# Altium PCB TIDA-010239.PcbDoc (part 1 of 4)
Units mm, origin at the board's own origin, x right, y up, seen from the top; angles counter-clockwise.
Board outline 160 x 175 mm, 4 copper layers (Top Layer, Inside 1, Inside 2, Bottom Layer), stack 1.787 mm thick; 299 components, 146 nets, 710 pads, 164 vias.
Unrouted connection lines stored in the file: 9.
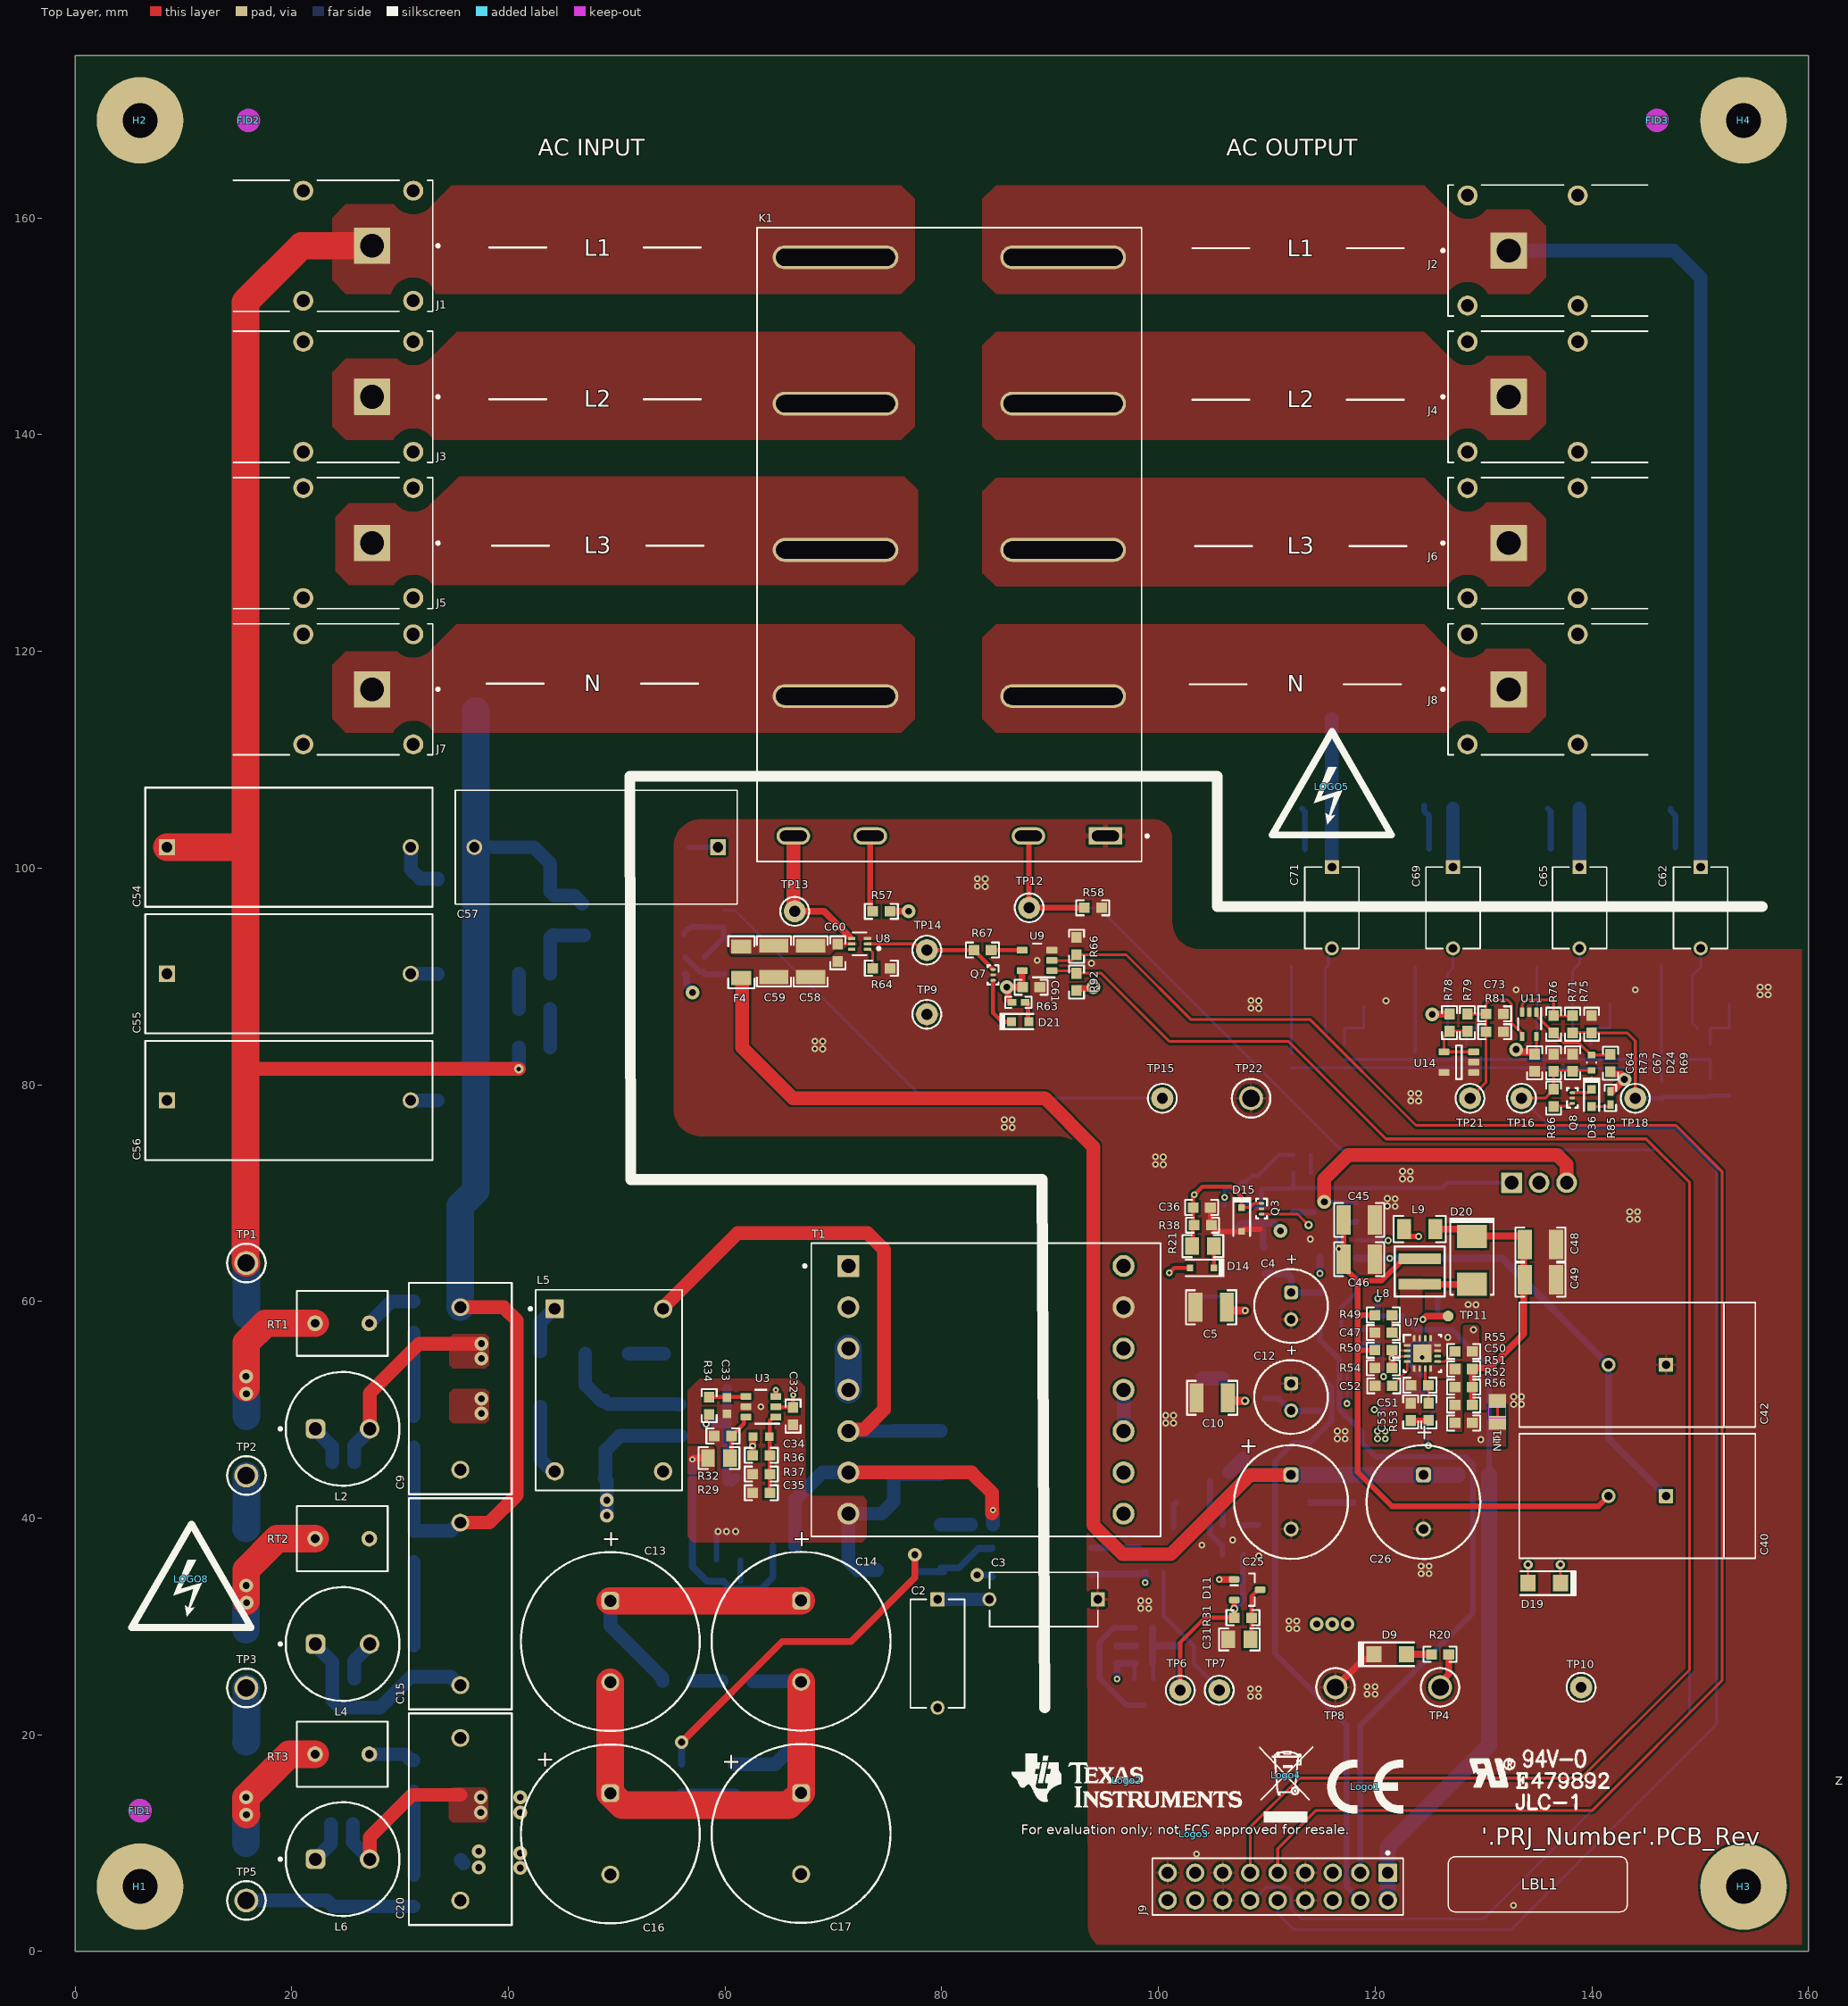
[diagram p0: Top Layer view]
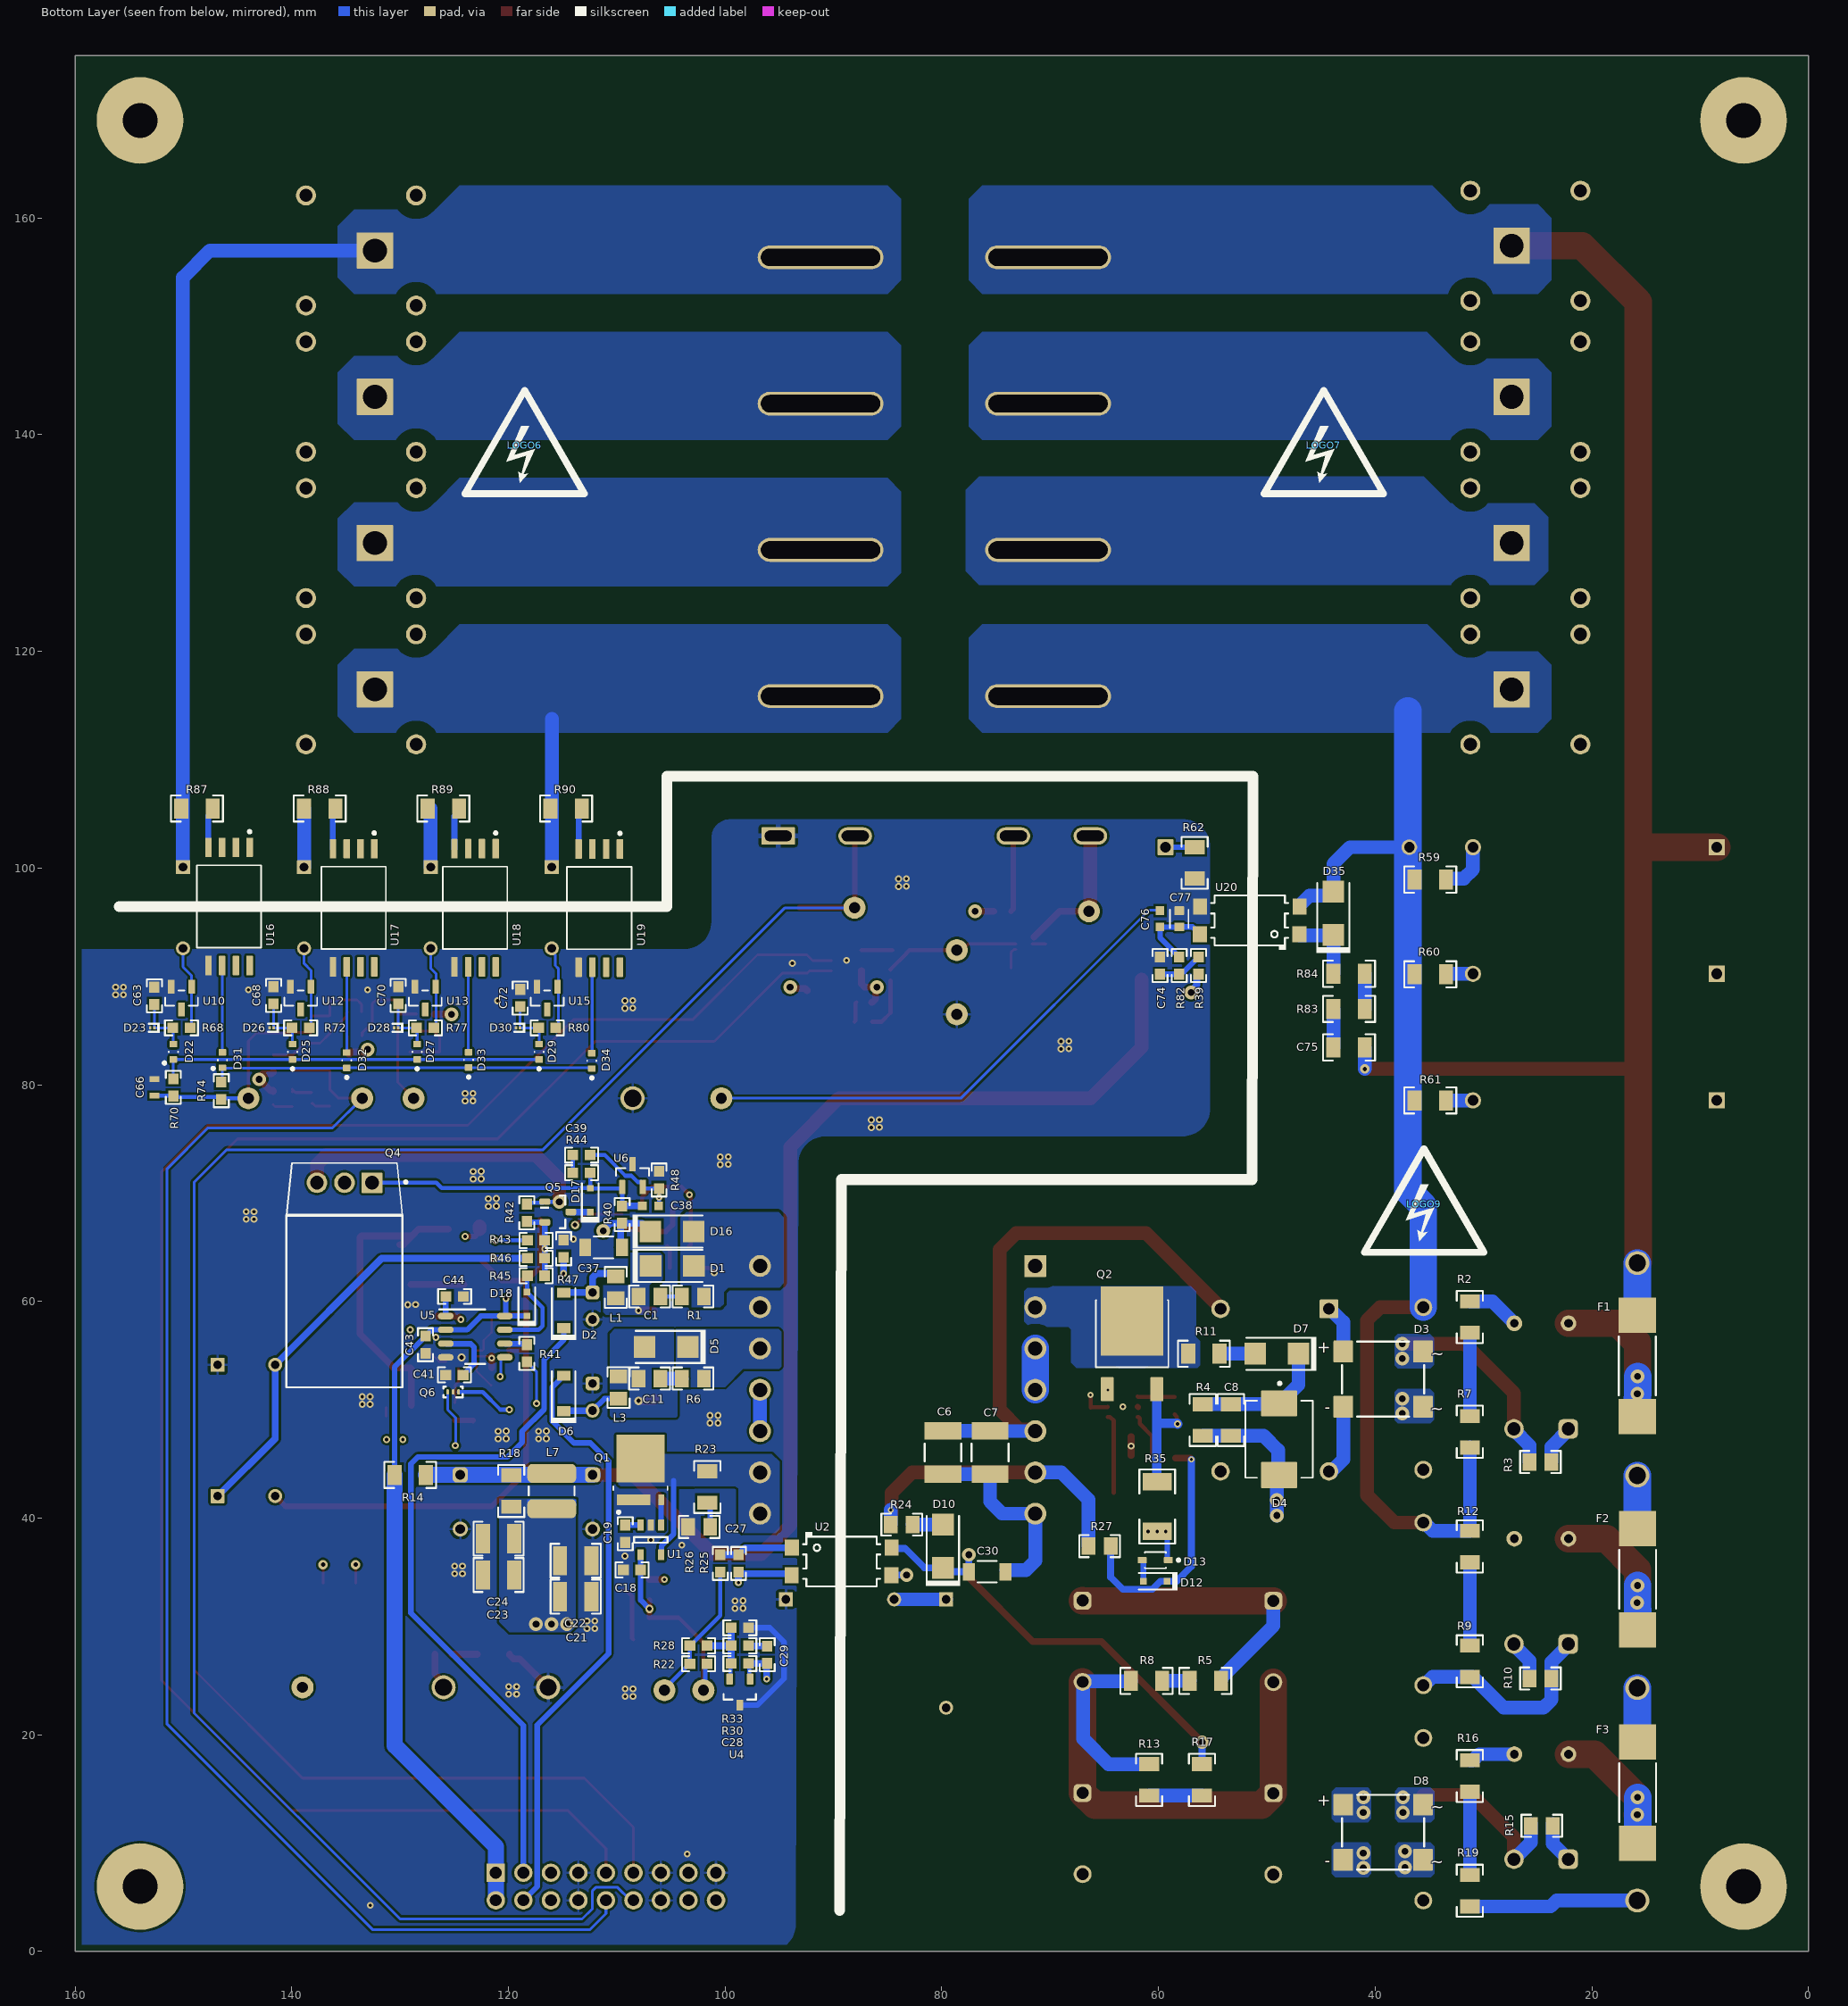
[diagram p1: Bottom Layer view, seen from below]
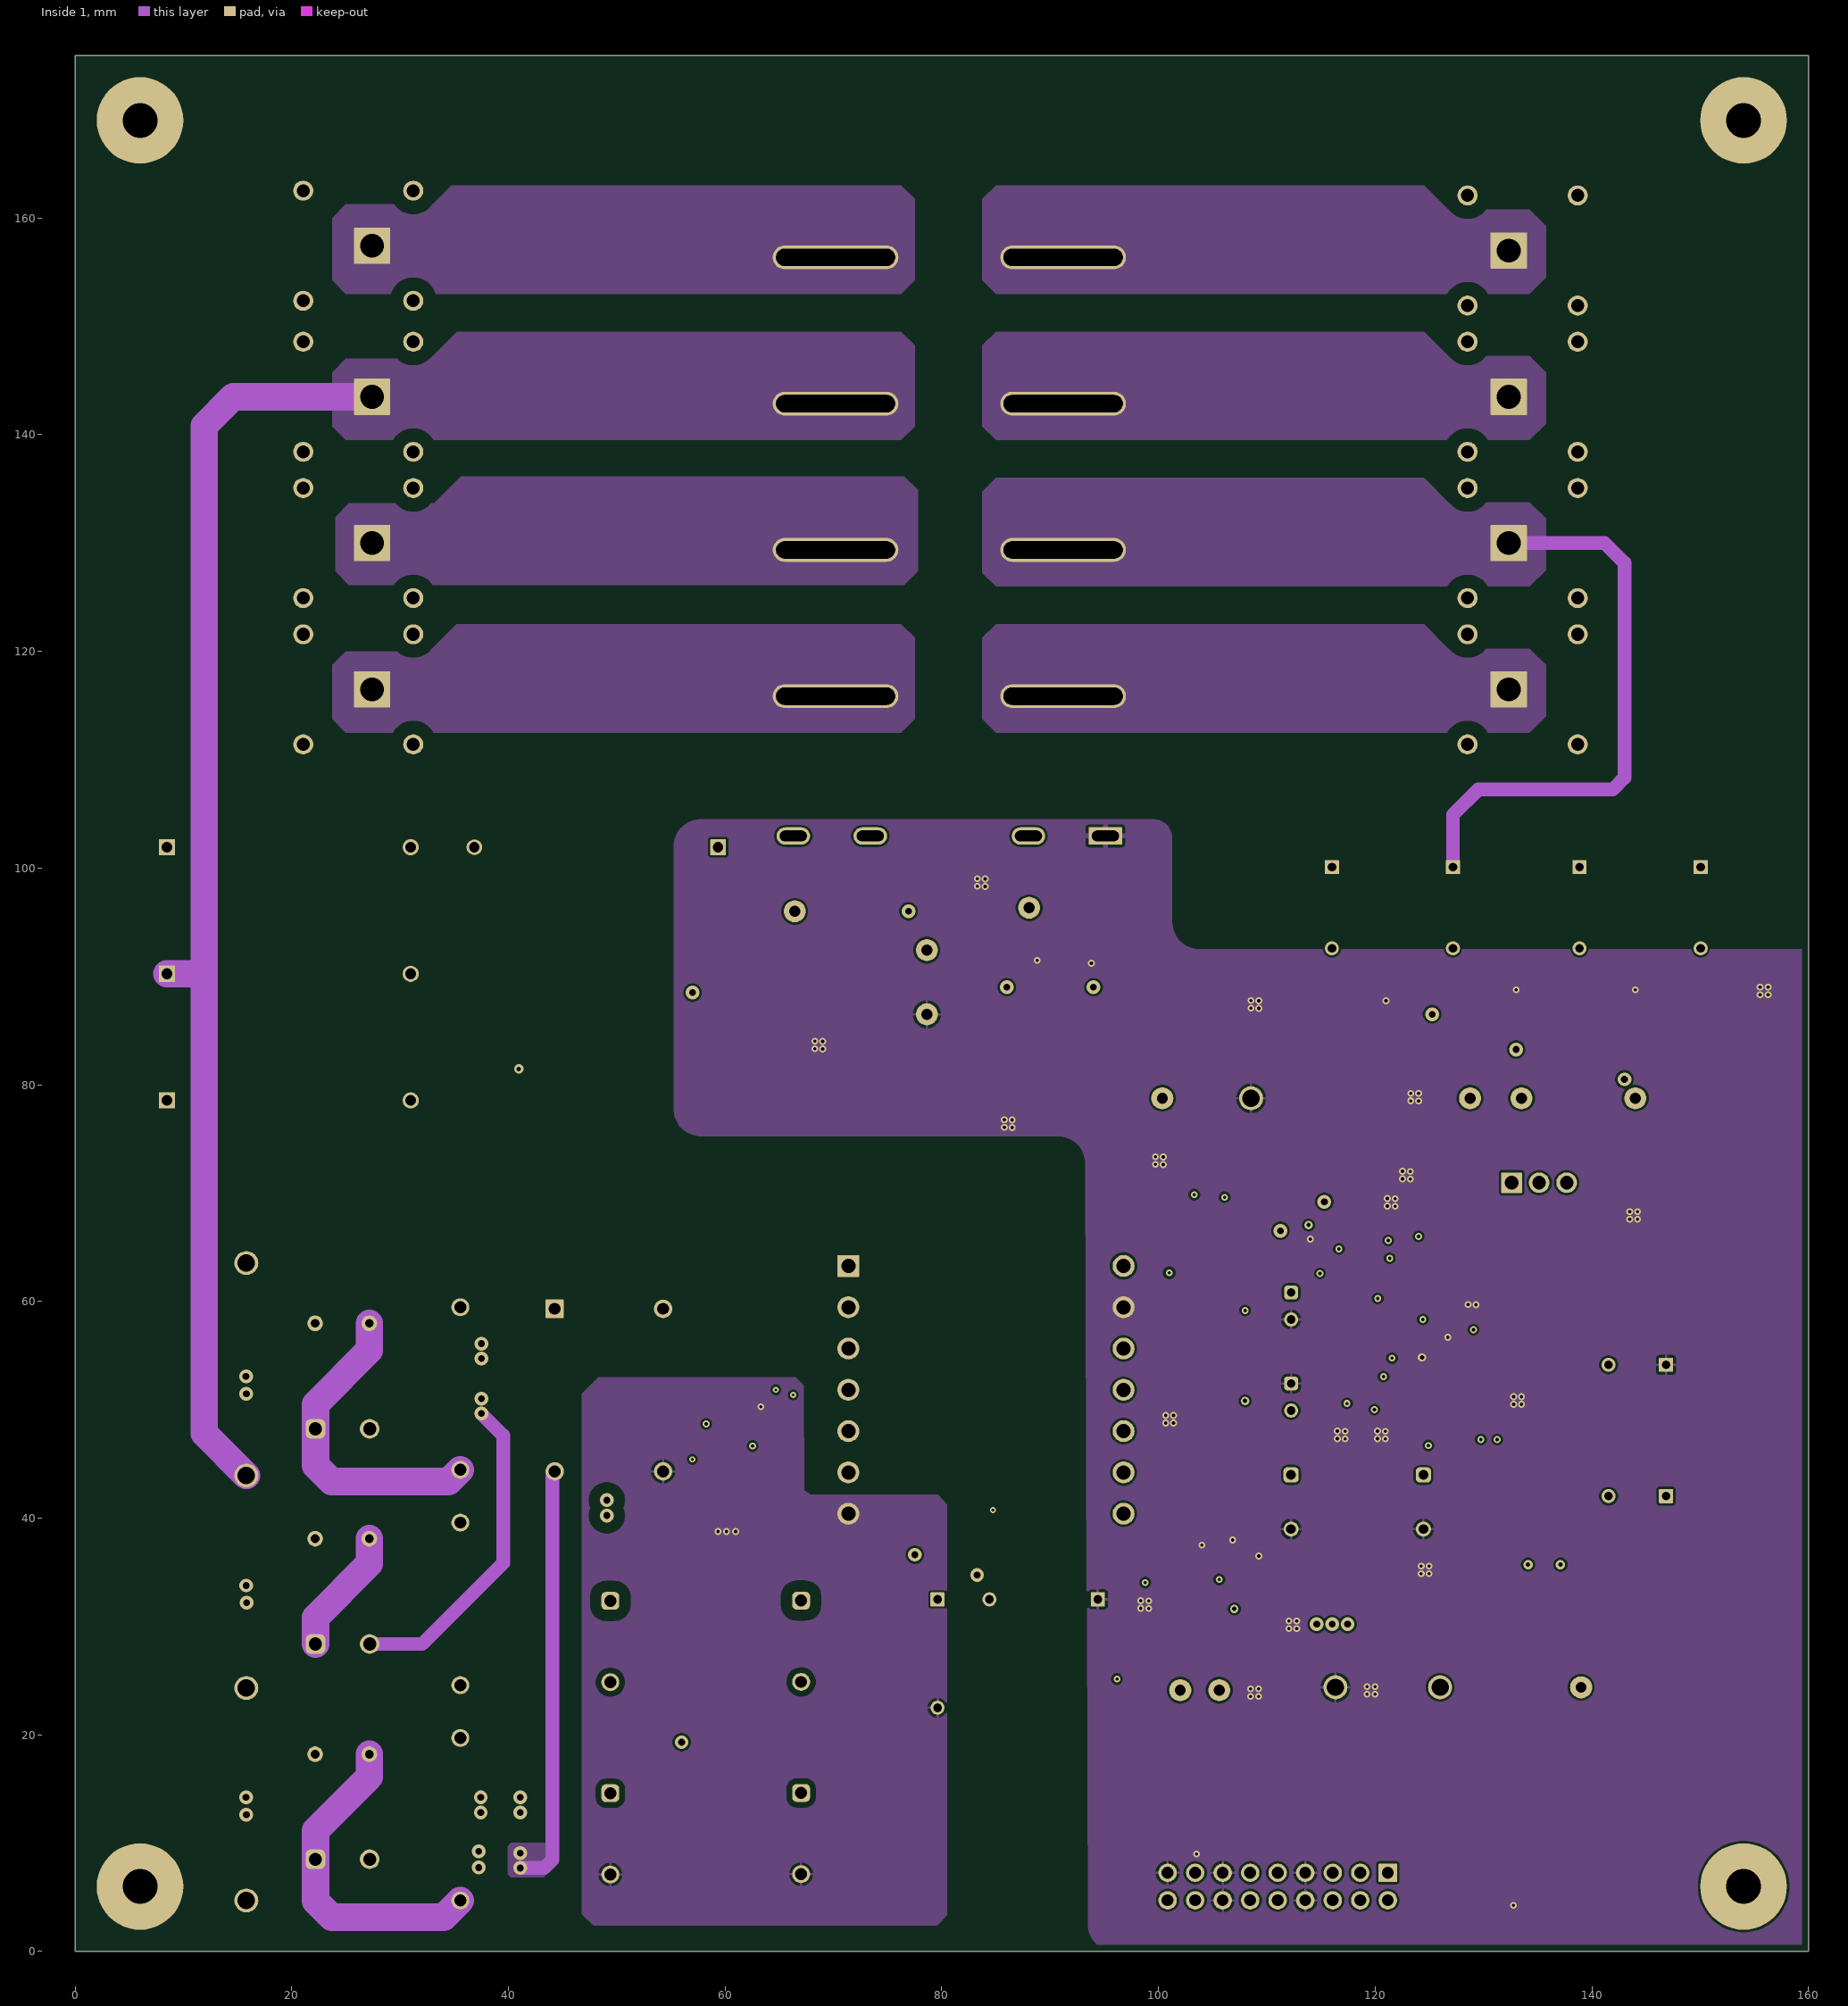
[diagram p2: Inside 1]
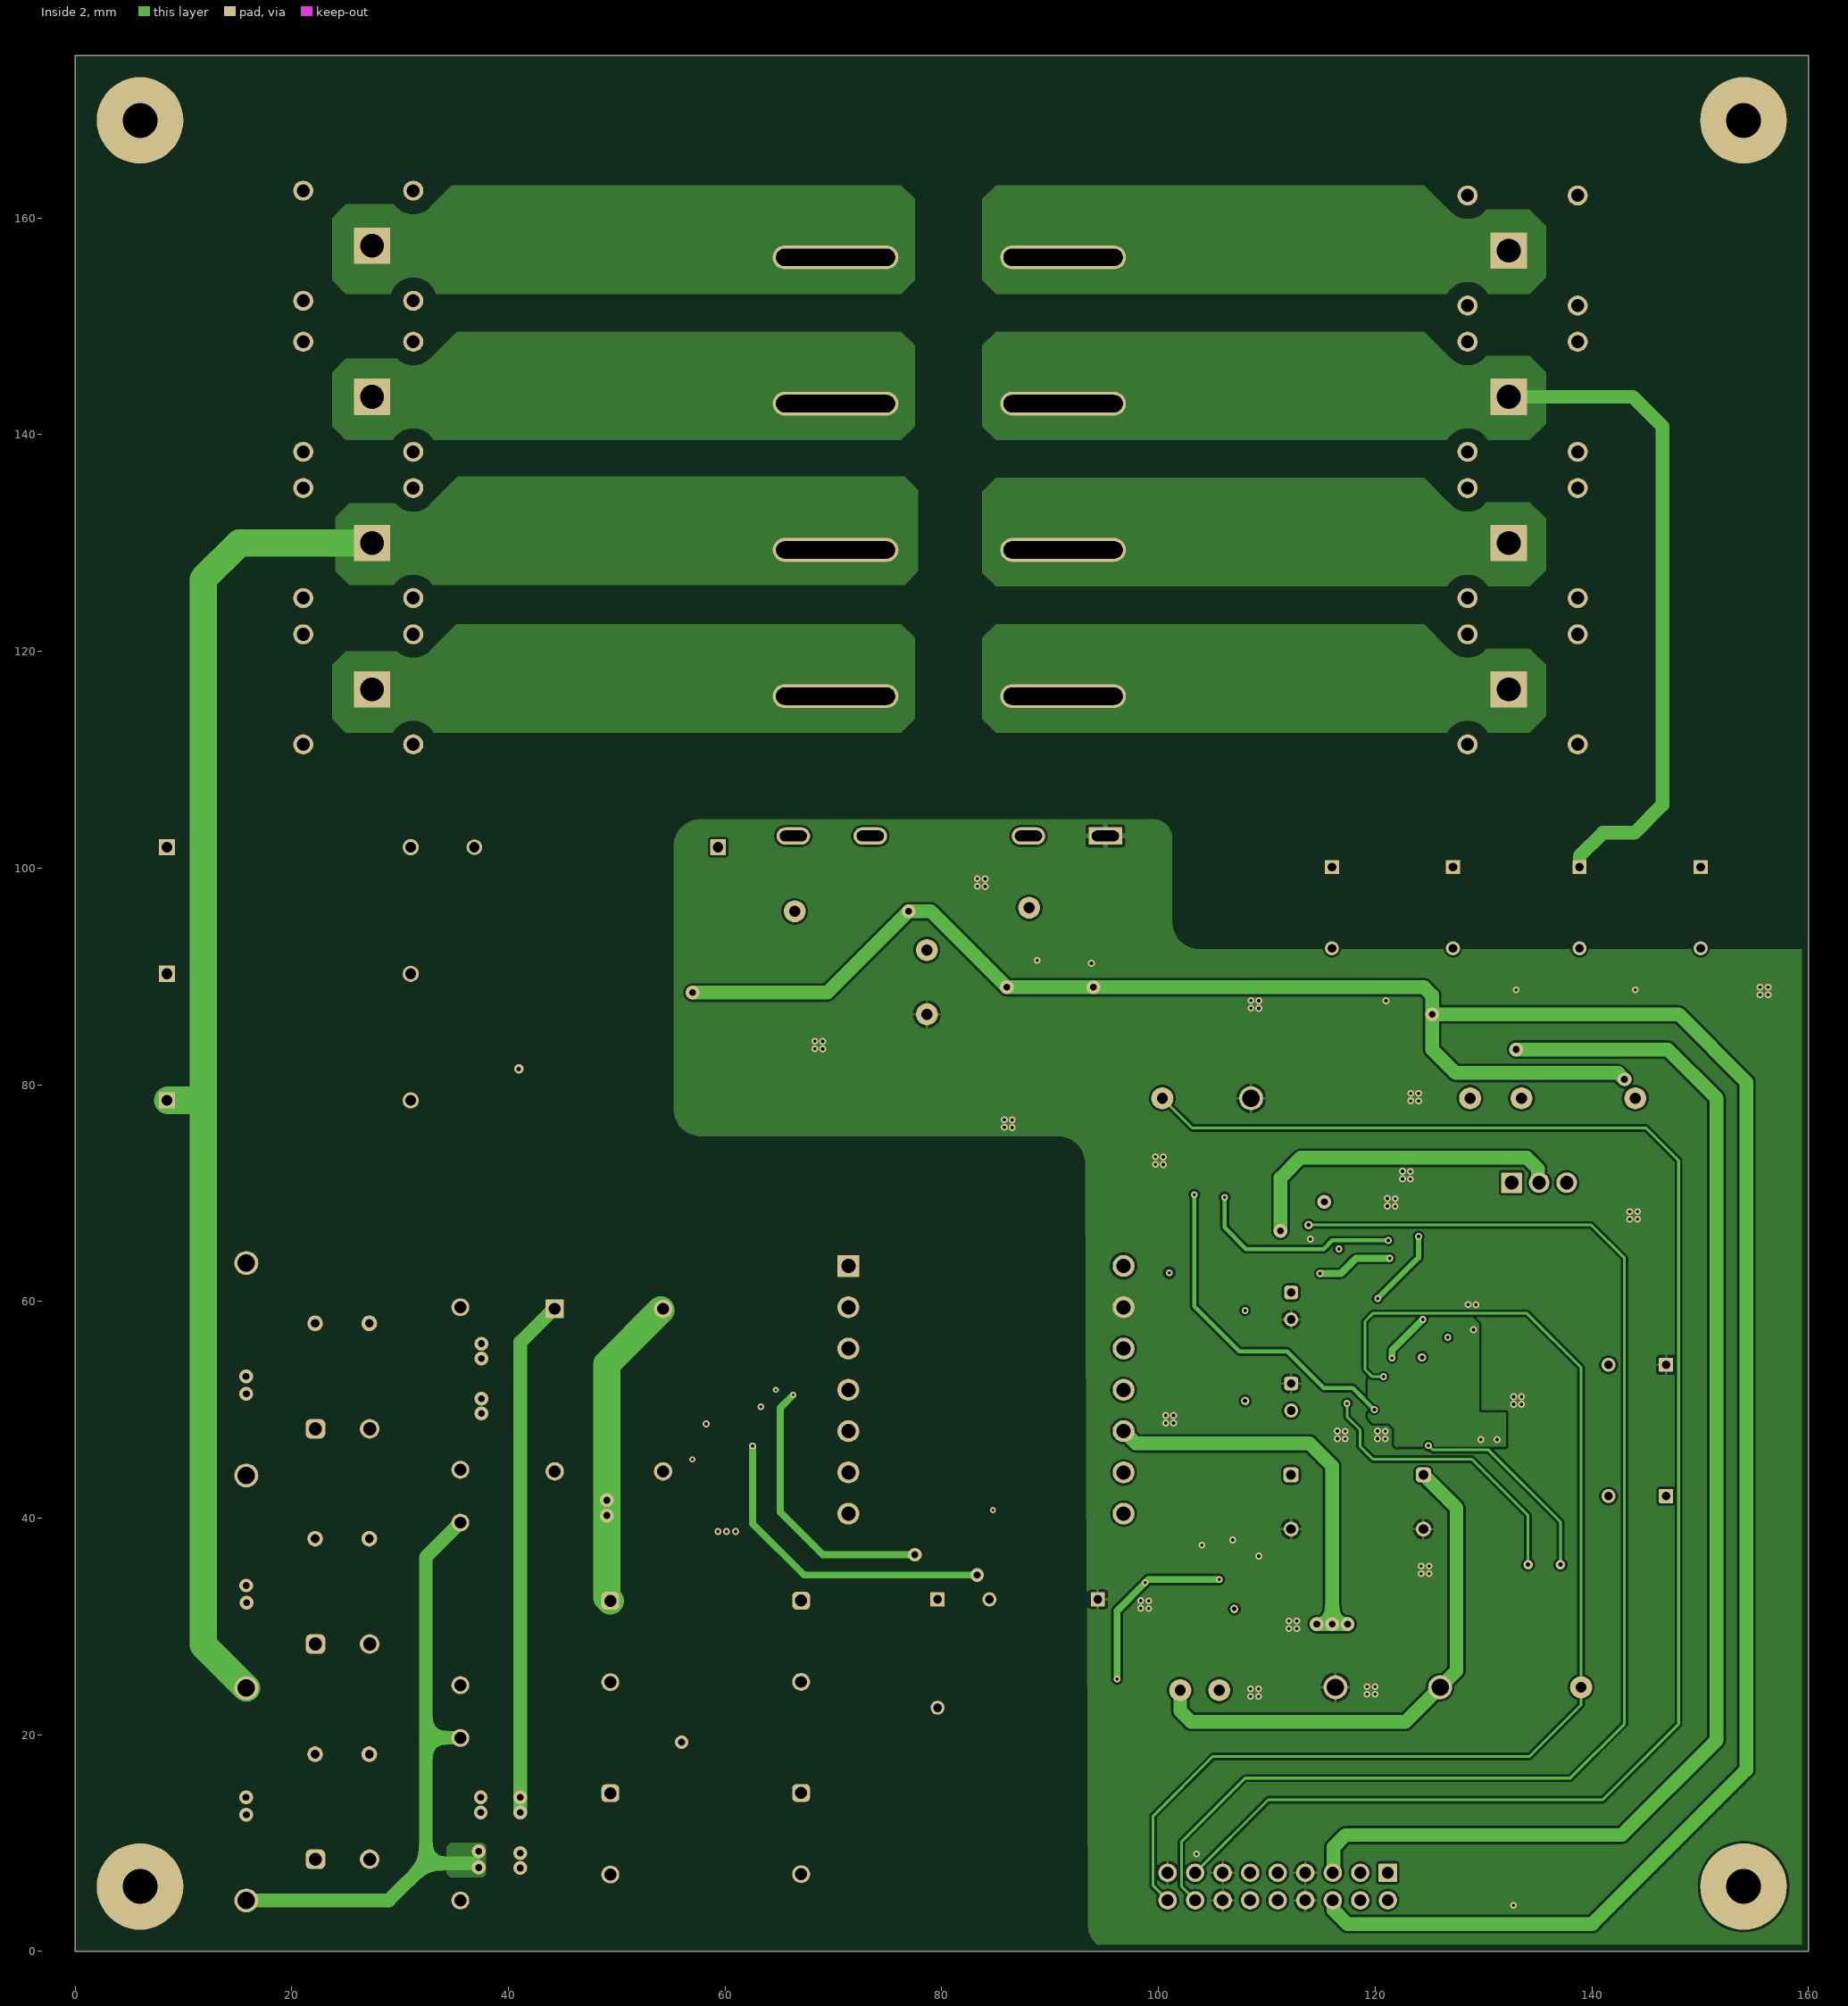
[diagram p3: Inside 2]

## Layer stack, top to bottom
Top Solder: solder mask 0.0102, Solder Resist, Dk 3.5
Top Layer: signal copper 0.0356
Dielectric 1: prepreg 0.0711, PP-006, Dk 4.1
Inside 1: signal copper 0.035
Dielectric1: core 1.5037, FR-4 High Tg, Dk 4.8
Inside 2: signal copper 0.035
Dielectric 2: prepreg 0.0711, PP-006, Dk 4.1
Bottom Layer: signal copper 0.0356
Bottom Solder: solder mask 0.0102, Solder Resist, Dk 3.5

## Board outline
0,0 0,175 160,175 160,0

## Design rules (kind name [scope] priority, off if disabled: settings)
AcuteAngle [All] p1: minimum=4.50000000000000E+0001 checktracksonly=FALSE
AssemblyTestPointUsage [All] p1: valid=2
BoardOutlineClearance BoardOutlineClearance_MountingHoles [OnCopper and InComponentClass('Mounting Holes')] p1: gap=1.016 ignorepadtopadclearanceinfootprint=FALSE
BoardOutlineClearance BoardOutlineClearance_Poly [OnCopper and IsPoly] p2: gap=0.635 ignorepadtopadclearanceinfootprint=FALSE
BoardOutlineClearance [OnCopper and Not InComponentClass('Logo') and not InComponentClass('FiducialMark') and not InRegion(1000,500,4000,800) and not InPoly] p3: gap=1.905 ignorepadtopadclearanceinfootprint=FALSE
Clearance "Schematic Clearance Constraint_9" [InNet('NetC8_2')] p1: gap=1.016 ignorepadtopadclearanceinfootprint=FALSE
Clearance "Schematic Clearance Constraint_8" [InNet('NetT1_3')] p2: gap=1.016 ignorepadtopadclearanceinfootprint=FALSE
Clearance "Schematic Clearance Constraint_7" [InNet('NetC6_1')] p3: gap=1.016 ignorepadtopadclearanceinfootprint=FALSE
Clearance "Schematic Clearance Constraint_6" [InNet('NetD7_2')] p4: gap=1.016 ignorepadtopadclearanceinfootprint=FALSE
Clearance "Schematic Clearance Constraint_5" [InNet('NetQ2_4')] p5: gap=1.016 ignorepadtopadclearanceinfootprint=FALSE
Clearance "Schematic Clearance Constraint_4" [InNet('NetR5_1')] p6: gap=1.016 ignorepadtopadclearanceinfootprint=FALSE
Clearance "Schematic Clearance Constraint_3" [InNet('NetR13_1')] p7: gap=0.508 ignorepadtopadclearanceinfootprint=FALSE
Clearance "Schematic Clearance Constraint_2" [InNet('NetC13_2')] p8: gap=0.508 ignorepadtopadclearanceinfootprint=FALSE
Clearance "Schematic Clearance Constraint" [InNet('+14V_SW')] p9: gap=0.254 ignorepadtopadclearanceinfootprint=FALSE
Clearance Clearance_HV_AC [InNetClass('HV')] p10: gap=1.25 ignorepadtopadclearanceinfootprint=FALSE
Clearance Clearance_Keepouts [((IsTrack Or IsArc) And Not InPoly) And IsFree and IsKeepOut vs ((IsTrack Or IsArc) And Not InPoly) And IsFree and IsKeepOut] p11: gap=0 ignorepadtopadclearanceinfootprint=FALSE
Clearance Clearance_Poly [InPolygon] p12: gap=0.203 ignorepadtopadclearanceinfootprint=FALSE
Clearance Clearance_FiducialMark [IsKeepOut and InComponentClass('FiducialMark') vs IsPad and InComponentClass('FiducialMark')] p13: gap=0 ignorepadtopadclearanceinfootprint=FALSE
Clearance [All] p14: gap=0.127 ignorepadtopadclearanceinfootprint=FALSE
ComponentClearance ComponentClearance_MountingHoles_FiducialMarks [InComponentClass('Mounting Holes') vs InComponentClass('FiducialMark')] p1: gap=1.27 collisioncheckmode=3 verticalgap=0.254 showdistances=FALSE
ComponentClearance ComponentClearance_Shunt [InComponentClass('Header') vs InComponentClass('Shunt')] p2: gap=0 collisioncheckmode=3 verticalgap=0 showdistances=FALSE
ComponentClearance ComponentClearance_Logo [InComponentClass('Logo')] p3: gap=1.27 collisioncheckmode=3 verticalgap=0.254 showdistances=FALSE
ComponentClearance ComponentClearance_ScrewToNut [(HasFootprint('NY PMS 440 0025 PH')) vs (HasFootprint('Keystone_1902C'))] p4: gap=0.127 collisioncheckmode=3 verticalgap=0.254 showdistances=FALSE
ComponentClearance ComponentClearance_MountingHoles [InComponentClass('Mounting Holes')] p5: gap=4 collisioncheckmode=3 verticalgap=2540 showdistances=FALSE
ComponentClearance ComponentClearance_SmallPassives [HasFootprint('0201*') or HasFootprint('0402*') or HasFootprint('0508') or HasFootprint('0603*') or HasFootprint('0612') or HasFootprint('0805*') or HasFootprint('0815*') or HasFootprint('0830*') or HasFootprint('1206*') or HasFootprint('1210*') or HasFootprint('1808*') or HasFootprint('1812*') or HasFootprint('1825*') or HasFootprint('2010*') or HasFootprint('2220*') or HasFootprint('2225*') or HasFootprint('2512*') or HasFootprint('2728*') or HasFootprint('3518*') vs HasFootprint('0201*') or HasFootprint('0402*') or HasFootprint('0508') or HasFootprint('0603*') or HasFootprint('0612') or HasFootprint('0805*') or HasFootprint('0815*') or HasFootprint('0830*') or HasFootprint('1206*') or HasFootprint('1210*') or HasFootprint('1808*') or HasFootprint('1812*') or HasFootprint('1825*') or HasFootprint('2010*') or HasFootprint('2220*') or HasFootprint('2225*') or HasFootprint('2512*') or HasFootprint('2728*') or HasFootprint('3518*')] p6: gap=0.38 collisioncheckmode=3 verticalgap=0.254 showdistances=FALSE
ComponentClearance ComponentClearance_THtoSMT [IsThruComponent vs IsSMTComponent] p7: gap=0.635 collisioncheckmode=3 verticalgap=0.762 showdistances=FALSE
ComponentClearance ComponentClearance_THtoTH [IsThruComponent vs IsThruComponent] p8 off: gap=0.762 collisioncheckmode=3 verticalgap=0.762 showdistances=FALSE
ComponentClearance [All] p9 off: gap=0.762 collisioncheckmode=3 verticalgap=0.254 showdistances=FALSE
DiffPairsRouting [All] p1: maxlimit=2.54 minlimit=0.254 mostfreqgap=0.254 toplayer_minwidth=0.381 toplayer_maxwidth=0.381 toplayer_prefwidth=0.381 midlayer1_minwidth=0.381 midlayer1_maxwidth=0.381 midlayer1_prefwidth=0.381 midlayer2_minwidth=0.381 midlayer2_maxwidth=0.381 midlayer2_prefwidth=0.381 bottomlayer_minwidth=0.381 bottomlayer_maxwidth=0.381 bottomlayer_prefwidth=0.381 maxuncoupledlength=25.4
FabricationTestPointUsage TestPointUsage [All] p1: valid=2 allowmultiple=FALSE
FabricationTestpoint Testpoint [All] p1: side=3 testpointundercomponent=TRUE minsize=1.016 maxsize=2.54 preferedsize=1.524 minholesize=0 maxholesize=1.016 preferedholesize=0.813 testpointgrid=0.025 allowsidetop=TRUE allowsidebottom=TRUE usegrid=TRUE gridtolerance=0
FanoutControl Fanout_LCC [IsLCC] p1: bgadir=Out bgaviamode=Centered fanoutstyle=Auto fanoutdirection=Alternating viagrid=0.025 // Fanout_LCC (Default Rule)
FanoutControl Fanout_BGA [IsBGA] p2: bgadir=Out bgaviamode=Centered fanoutstyle=Auto fanoutdirection=Alternating viagrid=0.025 // Fanout_BGA (Default Rule)
FanoutControl Fanout_Default [All] p4: bgadir=Out bgaviamode=Centered fanoutstyle=Auto fanoutdirection=Alternating viagrid=0.025 // Fanout_Default (Default Rule)
FanoutControl Fanout_Small [(CompPinCount < 5)] p5: bgadir=Out bgaviamode=Centered fanoutstyle=Auto fanoutdirection=OutThenIn viagrid=0.025 // Fanout_Small (Default Rule)
Height [All] p1: minheight=0 maxheight=27.94 prefheight=12.7
HoleSize HoleSize_Relay [(InNetClass('HV') AND InPadClass('All Pads'))] p1: absolutevalues=TRUE maxlimit=11.049 minlimit=0.025 maxpercent=80.000 minpercent=20.000
HoleSize [All] p2: absolutevalues=TRUE maxlimit=6.375 minlimit=0.2 maxpercent=80.000 minpercent=20.000
MinimumAnnularRing MinimumAnnularRing_ThermalPadVias [IsVia and InAnyComponent] p1: minimumring=0.1
MinimumAnnularRing [All] p2: minimumring=0.1
MinimumSolderMaskSliver MinimumSolderMaskSliver_ISO1212 [HasFootprint('DBQ0016A_N')] p1: minsoldermaskwidth=0.032
MinimumSolderMaskSliver MinimumSolderMaskSliver_TPS6513 [HasFootprint('RGE0024B')] p2: minsoldermaskwidth=0.046
MinimumSolderMaskSliver MinimumSolderMaskSliver_TLV7011 [HasFootprint('DCK0005A_N')] p3: minsoldermaskwidth=0.046
MinimumSolderMaskSliver MinimumSolderMaskSliver_TPS55330 [HasFootprint('RTE0016C_NV')] p4: minsoldermaskwidth=0.056
MinimumSolderMaskSliver MinimumSolderMaskSliver_INA293 [HasFootprint('DBV0005A_M')] p5: minsoldermaskwidth=0.097
MinimumSolderMaskSliver MinimumSolderMaskSliver_TPS7A3901_1 [HasFootprint('DSC0010J')] p6: minsoldermaskwidth=0.056
MinimumSolderMaskSliver MinimumSolderMaskSliver_Res [HasFootprint('RESC1005X40X25NL05T10')] p7: minsoldermaskwidth=0.046
MinimumSolderMaskSliver MinimumSolderMaskSliver_Logo [InComponentClass('Logo') vs InComponentClass('Logo')] p8: minsoldermaskwidth=0.018
MinimumSolderMaskSliver [All] p9: minsoldermaskwidth=0.1
PlaneConnect [All] p1: planeconnectstyle=Direct reliefexpansion=0.254 reliefentries=4 reliefconductorwidth=0.254 reliefairgap=0.254
PolygonConnect PolygonConnect_4 [All vs IsNamedPolygon('LAYER_2_LINE1_IN_P1412') Or IsNamedPolygon('LAYER_2_LINE1_OUT_P1420') Or IsNamedPolygon('LAYER_2_LINE2_IN_P1414') Or IsNamedPolygon('LAYER_2_LINE2_OUT_P1422') Or IsNamedPolygon('LAYER_2_LINE3_IN_P1416') Or IsNamedPolygon('LAYER_2_LINE3_OUT_P1424') Or IsNamedPolygon('LAYER_2_N_IN_P1418') Or IsNamedPolygon('LAYER_2_N_OUT_P1426')] p1: connectstyle=Direct reliefconductorwidth=0.254 reliefentries=4 polygonreliefangle="90 Angle" airgapwidth=0.254
PolygonConnect PolygonConnect_3 [All vs IsNamedPolygon('LAYER_1_LINE1_IN_P1411') Or IsNamedPolygon('LAYER_1_LINE1_OUT_P1419') Or IsNamedPolygon('LAYER_1_LINE2_IN_P1413') Or IsNamedPolygon('LAYER_1_LINE2_OUT_P1421') Or IsNamedPolygon('LAYER_1_LINE3_IN_P1415') Or IsNamedPolygon('LAYER_1_LINE3_OUT_P1423') Or IsNamedPolygon('LAYER_1_N_IN_P1417') Or IsNamedPolygon('LAYER_1_N_OUT_P1425')] p2: connectstyle=Direct reliefconductorwidth=0.254 reliefentries=4 polygonreliefangle="90 Angle" airgapwidth=0.254
PolygonConnect PolygonConnect_2 [All vs IsNamedPolygon('TOP_LAYER_N_IN_P1382') Or IsNamedPolygon('TOP_LAYER_N_OUT_P1366') Or IsNamedPolygon('BOTTOM_LAYER_N_IN_P1390') Or IsNamedPolygon('BOTTOM_LAYER_N_OUT_P1392')] p3: connectstyle=Direct reliefconductorwidth=0.254 reliefentries=4 polygonreliefangle="90 Angle" airgapwidth=0.254
PolygonConnect PolygonConnect_1 [All vs IsNamedPolygon('TOP_LAYER_LINE1_IN_P1378') Or IsNamedPolygon('TOP_LAYER_LINE1_OUT_P1370') Or IsNamedPolygon('TOP_LAYER_LINE2_IN_P1374') Or IsNamedPolygon('TOP_LAYER_LINE2_OUT_P1330') Or IsNamedPolygon('TOP_LAYER_LINE3_IN_P1380') Or IsNamedPolygon('TOP_LAYER_LINE3_OUT_P1372') Or IsNamedPolygon('BOTTOM_LAYER_LINE1_IN_P1256') Or IsNamedPolygon('BOTTOM_LAYER_LINE1_OUT_P1398') Or IsNamedPolygon('BOTTOM_LAYER_LINE2_IN_P1386') Or IsNamedPolygon('BOTTOM_LAYER_LINE2_OUT_P1396') Or IsNamedPolygon('BOTTOM_LAYER_LINE3_IN_P1388') Or IsNamedPolygon('BOTTOM_LAYER_LINE3_OUT_P1394')] p4: connectstyle=Direct reliefconductorwidth=0.254 reliefentries=4 polygonreliefangle="90 Angle" airgapwidth=0.254
PolygonConnect [InNetClass('All Nets')] p5: thpad.connectstyle=Relief thpad.reliefconductorwidth=0.254 thpad.reliefentries=4 thpad.polygonreliefangle="90 Angle" thpad.airgapwidth=0.254 smdpad.connectstyle=Direct smdpad.reliefconductorwidth=0.254 smdpad.reliefentries=4 smdpad.polygonreliefangle="90 Angle" smdpad.airgapwidth=0.254 via.connectstyle=Direct via.reliefconductorwidth=0.254 via.reliefentries=4 via.polygonreliefangle="90 Angle" via.airgapwidth=0.254
RoutingVias ThermalPadVias [IsVia and InAnyComponent] p1: holewidth=0.2 width=0.5 viastyle="Through Hole" minholewidth=0.2 minwidth=0.5 maxholewidth=0.33 maxwidth=0.6
RoutingVias [All] p2: holewidth=0.406 width=0.864 viastyle="Through Hole" minholewidth=0.152 minwidth=0.381 maxholewidth=1.016 maxwidth=1.651
SilkToBoardRegionClearance [Not ((IsComment or IsDesignator) And (Hide <> 'False')) and not InRegion(1000,500,4000,800)] p1:
SilkToSilkClearance SilkToSilkClearance_Pb-FreeLogo [(HasFootprint('Pb-Free_Overlay_Medium') OR HasFootprint('Pb-Free_Overlay_Small')) vs (HasFootprint('Pb-Free_Overlay_Medium') OR HasFootprint('Pb-Free_Overlay_Small'))] p1: silktosilkclearance=0
SilkToSilkClearance [All] p2: silktosilkclearance=0.051
SilkToSolderMaskClearance SilkToComponentPadClearance_FillArea [IsFill and InAnycomponent] p1: minsilkscreentomaskgap=0.038 clearancetoexposedcopper=TRUE
SilkToSolderMaskClearance SilkToComponentPadClearance_Pad [IsPad and InAnycomponent] p2: minsilkscreentomaskgap=0.076 clearancetoexposedcopper=TRUE
SilkToSolderMaskClearance SilkToComponentPadClearance_1 [(IsPad or IsFill or IsRegion) and InAnycomponent] p3: minsilkscreentomaskgap=0.127 clearancetoexposedcopper=TRUE
SilkToSolderMaskClearance "Silk to Solder Mask Opening" [All] p4: minsilkscreentomaskgap=0.076 clearancetoexposedcopper=FALSE
SolderMaskExpansion [All] p1 off: expansion=0.05 istentingtop=FALSE
SupplyNets "Schematic Supply Nets_7" [InNet('5V')] p1: voltage=0.000
SupplyNets "Schematic Supply Nets_5" [InNet('PGND')] p2: voltage=0.000
SupplyNets "Schematic Supply Nets_3" [InNet('AGND2')] p3: voltage=0.000
SupplyNets "Schematic Supply Nets_2" [InNet('12V')] p4: voltage=0.000
SupplyNets "Schematic Supply Nets_1" [InNet('3V3')] p5: voltage=0.000
SupplyNets "Schematic Supply Nets" [InNet('GND')] p6: voltage=0.000
Width Width_5V [All] p1 off: maxlimit=2.54 minlimit=0.254 preferedwidth=0.762
Width Width_-12a [InNet('-12Va')] p2 off: maxlimit=1.27 minlimit=0.254 preferedwidth=0.508
Width Width_12a [InNet('+12Va')] p3 off: maxlimit=1.27 minlimit=0.254 preferedwidth=0.508
Width Width_12VP [InNet('12V_In')] p4 off: maxlimit=1.27 minlimit=0.254 preferedwidth=0.762
Width Width_3_3 [InNet('3V3')] p5 off: maxlimit=2.54 minlimit=0.254 preferedwidth=0.762
Width Width_GND [InNet('PGND')] p6 off: maxlimit=0.762 minlimit=0.254 preferedwidth=0.508
Width Width_AC [InNetClass('HV')] p7 off: maxlimit=5.08 minlimit=0.508 preferedwidth=2.54
Width [All] p8 off: maxlimit=0.508 minlimit=0.203 preferedwidth=0.254 checkconnectedcopper=TRUE
14 further rules are at their usual default settings.

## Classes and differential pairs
component class TIDA-010239_HPGP_ZC: C74 C75 C76 C77 D35 R39 R82 R83 R84 TP15 U20
net class HV: LINE1_IN LINE1_OUT LINE2_IN LINE2_OUT LINE3_IN LINE3_OUT N_IN N_OUT NetR87_1 NetR88_1 NetR89_1 NetR90_1
component class TIDA-010239_Weld_Detection: C62 C63 C64 C65 C66 C67 C68 C69 C70 C71 C72 C73 D22 D23 D24 D25 D26 D27 D28 D29 D30 D36 Q8 R68 R69 R70 R71 R72 R73 R74 R75 R76 R77 R78 R79 R80 R81 R85 R86 TP16 TP18 TP21 TP22 U10 U11 U12 U13 U14 U15
component class TIDA-010239_Weld_Detection_B: D31 D32 D33 D34 R87 R88 R89 R90 U16 U17 U18 U19
component class TIDA-010239_Relay_DRV: C54 C55 C56 C57 C58 C59 C60 C61 D21 F4 J1 J2 J3 J4 J5 J6 J7 J8 K1 Q7 R57 R58 R59 R60 R61 R62 R63 R64 R66 R67 R92 TP12 TP13 TP14 U8 U9
component class TIDA-010239_PWR_Flyback: C1 C2 C3 C4 C5 C6 C7 C8 C9 C10 C11 C12 C13 C14 C15 C16 C17 C18 C19 C20 C21 C22 C23 C24 C25 C26 C27 C28 C29 C30 C31 C32 C33 C34 C35 D1 D2 D3 D4 D5 D6 D7 D8 D9 D10 D11 D12 D13 F1 F2 F3 L1 L2 L3 L4 L5 L6 L7 Q1 Q2 R1 R2 R3 R4 R5 R6 R7 R8 R9 R10 R11 R12 R13 R14 R15 R16 R17 R18 R19 R20 R22 R23 R24 R25 R26 R27 R28 R29 R30 R31 R32 R33 R34 R35 R36 R37 RT1 RT2 RT3 T1 TP1 TP2 TP3 TP4 TP5 TP6 TP7 TP8 TP9 U1 U2 U3 U4
component class TIDA-010239_PWR_Backup: C36 C37 C38 C39 C40 C41 C42 C43 C44 C45 C46 C47 C48 C49 C50 C51 C52 C53 D14 D15 D16 D17 D18 D19 D20 L8 L9 NT1 Q3 Q4 Q5 Q6 R21 R38 R40 R41 R42 R43 R44 R45 R46 R47 R48 R49 R50 R51 R52 R53 R54 R55 R56 TP10 TP11 U5 U6 U7
component class TIDA-010239_Connector: J9
component class "Mounting Holes": H1 H2 H3 H4
component class Logo: Logo2
component class TIDA-010239_Hardware: FID1 FID2 FID3 H1 H2 H3 H4 LBL1 Logo1 Logo2 Logo3 Logo4 LOGO5 LOGO6 LOGO7 LOGO8 LOGO9 ZZ1 ZZ2 ZZ3 ZZ4
component class FiducialMark: FID1 FID2 FID3
component class AssemblyNote: ZZ1 ZZ2 ZZ3 ZZ4
component class Label: LBL1

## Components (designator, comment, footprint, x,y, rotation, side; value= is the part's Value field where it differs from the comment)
C1 "GRM21A5C2E680JW01D" 0805_HV 106.973,60.45 r180 bottom value=68pF
C2 "DE1E3RA332MN4AP01F" FP-DE1E3RA332MN4AP01F_RADIAL_CAP_10MM0_5MM0_10MM0-MFG 79.6,27.5 r270 top value=3.3nF
C3 "DE1E3RA332MN4AP01F" FP-DE1E3RA332MN4AP01F_RADIAL_CAP_10MM0_5MM0_10MM0-MFG 89.4,32.5 r180 top value=3.3nF
C4 "860010473007" WCAP-ATG8_D6.3H11 112.233,59.58 r90 top locked value=100µF
C5 "CC1210KKX7R8BB226" 1210_270 104.853,59.46 r180 top value=22uF
C6 "C1812W104KDRACTU" 1812_254 79.891,46.044 r270 bottom value=0.1uF
C7 "C1812W104KDRACTU" 1812_254 75.551,46.044 r270 bottom value=0.1uF
C8 "VJ1206Y102KXEAT5Z" 1206 53.318,49.05 r90 bottom value=1000pF
C9 "890493425009CS" WCAP-FTBE_L18W8.5H15 35.563,51.96 r90 top value=100nF
C10 "CC1210KKX7R8BB226" 1210_270 104.95,51.1 r0 top value=22uF
C11 "GRM21A5C2E680JW01D" 0805_HV 106.973,52.89 r180 bottom value=68pF
C12 "860010473007" WCAP-ATG8_D6.3H11 112.233,51.18 r90 top locked value=100µF
C13 "860021380017" WCAP-ATG5_D16H25 49.403,28.61 r90 top value=68µF
C14 "860021380017" WCAP-ATG5_D16H25 67.013,28.636 r90 top value=68µF
C15 "890493425009CS" WCAP-FTBE_L18W8.5H15 35.563,32.085 r90 top value=100nF
C16 "860021380017" WCAP-ATG5_D16H25 49.403,10.86 r90 top value=68µF
C17 "860021380017" WCAP-ATG5_D16H25 67.013,10.89 r90 top value=68µF
C18 "C1608X7R1H104K080AA" 0603 108.593,35.22 r0 bottom value=0.1uF
C19 "GRM188Z71C225KE43" 0603 109.223,38.56 r270 bottom value=2.2uF
C20 "890493425009CS" WCAP-FTBE_L18W8.5H15 35.563,12.21 r90 top value=100nF
C21 "CC1210KKX7R8BB226" 1210_270 113.792,32.75 r0 bottom value=22uF
C22 "CC1210KKX7R8BB226" 1210_270 113.792,36.068 r0 bottom value=22uF
C23 "CC1210KKX7R8BB226" 1210_270 120.904,34.75 r180 bottom value=22uF
C24 "CC1210KKX7R8BB226" 1210_270 120.904,38.1 r180 bottom value=22uF
C25 "860040475009" WCAP-ATUL_D10H20 112.233,41.49 r90 top locked value=680µF
C26 "860040475009" WCAP-ATUL_D10H20 124.446,41.488 r90 top locked value=680µF
C27 "GRM21A5C2E101JW01D" 0805_HV 102.393,39.18 r0 bottom value=100pF
C28 "C0603C222K5RAC" 0603 98.643,26.58 r0 bottom value=2200pF
C29 "C1608X7R1H104K080AA" 0603 96.123,27.39 r90 bottom value=0.1uF
C30 "CL31B106KBHNNNE" 1206_180 75.813,35.05 r180 bottom value=10uF
C31 "C2012X7R1E475K125AB" 0805_HV 107.459,28.8 r180 top value=4.7uF
C32 "C1608X7R1H104K080AA" 0603 66.273,49.41 r270 top value=0.1uF
C33 "885012006057" WCAP-CSGP_0603_L1.6W0.8H0.8_Reflow 60.164,50.376 r270 top value=100pF
C34 "885012206093" WCAP-CSGP_0603_L1.6W0.8H0.8_Reflow 63.333,47.52 r0 top value=47nF
C35 "C0603C221J5GACTU" 0603 63.333,42.33 r0 top value=220pF
C36 "885012206087" 0603 103.983,68.67 r0 top value=4700pF
C37 "CL31B106KBHNNNE" 1206_180 111.213,64.98 r0 bottom value=10uF
C38 "885012006057" WCAP-CSGP_0603_L1.6W0.8H0.8_Reflow 106.899,68.81 r180 bottom value=100pF
C39 "C1608X7R1H104K080AA" 0603 113.253,73.5 r180 bottom value=0.1uF
C40 "PHVL-3R9V255-R" FP-PHVL-3R9V255-R_RADIAL-MFG 144.183,42.03 r180 top value=2.5F
C41 "C1608X7R1H104K080AA" 0603 124.983,53.22 r0 bottom value=0.1uF
C42 "PHVL-3R9V255-R" FP-PHVL-3R9V255-R_RADIAL-MFG 144.183,54.15 r180 top value=2.5F
C43 "C1608X7R1H104K080AA" 0603 127.653,56.01 r270 bottom value=0.1uF
C44 "C1608X7R1H104K080AA" 0603 124.968,60.452 r180 bottom value=0.1uF
C45 "CC1210KKX7R8BB226" 1210_270 118.523,67.51 r180 top value=22uF
C46 "CC1210KKX7R8BB226" 1210_270 118.523,63.892 r180 top value=22uF
C47 "C1608X7R1H104K080AA" 0603 120.753,57.119 r0 top value=0.1uF
C48 "CC1210KKX7R8BB226" 1210_270 135.25,65.25 r180 top value=22uF
C49 "CC1210KKX7R8BB226" 1210_270 135.25,62 r180 top value=22uF
C50 "CC0603CRNPO0BN6R8" 0603 128.163,53.76 r180 top value=6.8pF
C51 "885012206081" 0603 124.113,52.266 r180 top value=470pF
C52 "C1608X7R1H104K080AA" 0603 120.784,52.201 r180 top value=0.1uF
C53 "C0603C103K5RACTU" 0603 123.273,49.806 r270 top value=0.01uF
C54 "B32923C3105M" B32923_20.5mm 19.734,101.918 r0 top value=1uF
C55 "B32923C3105M" B32923_20.5mm 19.734,90.234 r0 top value=1uF
C56 "B32923C3105M" B32923_20.5mm 19.734,78.55 r0 top value=1uF
C57 "PHE850ED6100MD18R06L2" FP-PHE850ED6100MD18R06L2_RADIAL-MFG 48.108,101.918 r180 top value=100nF
C58 "CC1210KKX7R8BB226" 1210_270 67.9,91.384 r90 top value=22uF
C59 "CC1210KKX7R8BB226" 1210_270 64.5,91.384 r90 top value=22uF
C60 "C1608X7R1H104K080AA" 0603 70.4,92.176 r270 top value=0.1uF
C61 "C1608X7R1H104K080AA" 0603 88.25,89 r0 top value=0.1uF
C62 "VY2102M29Y5US6TV7" FP-VY2102M29Y5US6TV7_RADIAL-MFG 150.036,96.33 r270 top value=1nF
C63 "C0603C470J1GACAUTO" 0603 152.672,88.2 r90 bottom value=47pF
C64 "C1608X7R1H104K080AA" 0603 134.713,82.029 r270 top value=0.1uF
C65 "VY2102M29Y5US6TV7" FP-VY2102M29Y5US6TV7_RADIAL-MFG 138.86,96.33 r270 top value=1nF
C66 "06033C101KAT2A" 0603S 152.672,79.75 r90 bottom value=100pF
C67 "C1608X7R1H104K080AA" 0603 138.213,82.029 r90 top value=0.1uF
C68 "C0603C470J1GACAUTO" 0603 141.672,88.25 r90 bottom value=47pF
C69 "VY2102M29Y5US6TV7" FP-VY2102M29Y5US6TV7_RADIAL-MFG 127.176,96.33 r270 top value=1nF
C70 "C0603C470J1GACAUTO" 0603 130.172,88.25 r90 bottom value=47pF
C71 "VY2102M29Y5US6TV7" FP-VY2102M29Y5US6TV7_RADIAL-MFG 116,96.33 r270 top value=1nF
C72 "C0603C470J1GACAUTO" 0603 118.922,88 r90 bottom value=47pF
C73 "C1608X7R1H104K080AA" 0603 131.019,86.538 r0 top value=0.1uF
C74 "GCM188R71E105KA64D" 0603 59.866,90.996 r90 bottom value=1uF
C75 "GRM31BR73A222KW01L" 1206 42.414,83.434 r180 bottom value=2200pF
C76 "885012206083" WCAP-CSGP_0603_L1.6W0.8H0.8_Reflow 59.866,95.314 r90 bottom value=1nF
C77 "CC0603KRX7R7BB224" FP-CC0603KRX7R7BB224_0603-MFG 58.088,95.314 r270 bottom value=220nF
D1 "SS1200-LTP" SMA 104.883,63.27 r180 bottom value=200V
D2 "MBR0540T1G" SOD-123 114.903,59.164 r90 bottom value=40V
D3 "TBS22M-TP" TBS4 39.273,52.83 r180 bottom value=1000V
D4 "SMCJ130A" FP-SMCJ130A_DO-214AB-MFG 48.873,47.28 r270 bottom
D5 "SS1200-LTP" SMA 105.439,55.8 r0 bottom value=200V
D6 "MBR0540T1G" SOD-123 114.903,51.502 r90 bottom value=40V
D7 "US1M-13-F" SMA 49.083,55.17 r0 bottom value=1000V
D8 "TBS22M-TP" TBS4 39.273,11.01 r180 bottom value=1000V
D9 "150120RS75000" WL_SMCW_RED_1206 121.388,27.432 r0 top value=Red
D10 "US1G-13-F" SMA 79.9,37.4 r90 bottom value=400V
D11 "BAT54SLT1G" SOT-23 108.183,33.39 r0 top value=30V
D12 "BAS20HT1G" SOD-323 60.303,34.17 r0 bottom value=200V
D13 "BZX384C43-E3-08" FP-BZX384C43-E3-08_SOD323-MFG 60.303,36.12 r0 bottom
D14 "BAS20HT1G" SOD-323 104.013,63.09 r180 top value=200V
D15 "SZMM3Z16VST1G" SOD-323 107.673,67.56 r270 top value=16V
D16 "SS1200-LTP" SMA 104.895,66.454 r180 bottom value=200V
D17 "BAS20HT1G" SOD-323 112.443,69.35 r90 bottom value=200V
D18 "BAS20HT1G" SOD-323 118.293,59.761 r90 bottom value=200V
D19 "150120RS75000" WL_SMCW_RED_1206 135.6,34 r180 top value=Red
D20 "MBRS2040LT3G" SMB 128.926,63.795 r270 top value=40V
D21 "150060GS75000" WL-SMCW_GREEN 87.237,85.815 r0 top value=Green
D22 "GSRB751S-40" FP-GSRB751S-40_SOD523-0 150.922,83.04 r90 bottom
D23 "GDZ5V1LP3-7" X3-DFN0603-2 152.862,85.25 r0 bottom value=5.1V
D24 "GSRB751S-40" FP-GSRB751S-40_SOD523-0 139.963,82.029 r90 top
D25 "GSRB751S-40" FP-GSRB751S-40_SOD523-0 139.922,83.04 r90 bottom
D26 "GDZ5V1LP3-7" X3-DFN0603-2 141.862,85.25 r0 bottom value=5.1V
D27 "GSRB751S-40" FP-GSRB751S-40_SOD523-0 128.422,83.04 r90 bottom
D28 "GDZ5V1LP3-7" X3-DFN0603-2 130.362,85.25 r0 bottom value=5.1V
D29 "GSRB751S-40" FP-GSRB751S-40_SOD523-0 117.172,83.04 r90 bottom
D30 "GDZ5V1LP3-7" X3-DFN0603-2 119.112,85.25 r0 bottom value=5.1V
D31 "GSRB751S-40" FP-GSRB751S-40_SOD523-0 146.402,82.27 r90 bottom
D32 "GSRB751S-40" FP-GSRB751S-40_SOD523-0 134.922,82.25 r90 bottom
D33 "GSRB751S-40" FP-GSRB751S-40_SOD523-0 123.672,82.29 r90 bottom
D34 "GSRB751S-40" FP-GSRB751S-40_SOD523-0 112.3,82.2 r90 bottom
D35 "US1M-13-F" SMA 43.864,95.822 r90 bottom value=1000V
D36 "150060GS75000" WL-SMCW_GREEN 139.963,78.779 r270 top value=Green
F1 "0443001.DR" FUSE_0443 15.813,54.06 r90 bottom
F2 "0443001.DR" FUSE_0443 15.783,34.365 r90 bottom
F3 "0443001.DR" FUSE_0443 15.783,14.67 r90 bottom
F4 "044001.5WR" 1206 61.5,91.3 r270 top
FID1 "Fiducial" Fiducial10-20 6,13 r90 top
FID2 "Fiducial" Fiducial10-20 16,169 r90 top
FID3 "Fiducial" Fiducial10-20 146,169 r90 top
H1 "NY PMS 440 0025 PH" "NY PMS 440 0025 PH" 6,6 r0 top
H2 "NY PMS 440 0025 PH" "NY PMS 440 0025 PH" 6,169 r0 top
H3 "NY PMS 440 0025 PH" "NY PMS 440 0025 PH" 154,6 r0 top
H4 "NY PMS 440 0025 PH" "NY PMS 440 0025 PH" 154,169 r0 top
J1 "FCR7350N" FP-FCR7350N_CONN_BANANA_JACK-MFG#1 16.422,157.43 r0 top
J2 "FCR7350N" FP-FCR7350N_CONN_BANANA_JACK-MFG#2 143.322,156.99 r180 top
J3 "FCR7350N" FP-FCR7350N_CONN_BANANA_JACK-MFG#1 16.422,143.49 r0 top
J4 "FCR7350N" FP-FCR7350N_CONN_BANANA_JACK-MFG#2 143.322,143.49 r180 top
J5 "FCR7350N" FP-FCR7350N_CONN_BANANA_JACK-MFG#1 16.422,129.99 r0 top
J6 "FCR7350N" FP-FCR7350N_CONN_BANANA_JACK-MFG#2 143.322,129.99 r180 top
J7 "FCR7350G" FP-FCR7350G_CONN_BANANA_JACK-MFG#1 16.422,116.49 r0 top
J8 "FCR7350G" FP-FCR7350G_CONN_BANANA_JACK-MFG#2 143.322,116.49 r180 top
J9 "61301821121" FP-61301821121_HDR18-MFG 111,6 r180 top
K1 "G9KC-4A1B DC12" "FP-G9KC-4A1B DC12_PTH_RELAY_58MM0_35MM0-MFG" 80.694,129.858 r90 top
L1 "74279205" 0805_HV 110.086,61.29 r90 bottom value="1000 ohm"
L2 "7447480151" WE-TI_1014 24.693,48.24 r0 top value=150uH
L3 "74279205" 0805_HV 109.833,52.05 r270 bottom value="1000 ohm"
L4 "7447480151" WE-TI_1014 24.693,28.38 r0 top value=150uH
L5 "7446121007" FP-7446121007_PTH_CMC_18MM5_13MM5-MFG 49.276,51.816 r270 top value=6.8mH
L6 "7447480151" WE-TI_1014 24.693,8.52 r0 top value=150uH
L7 "7447730" WE-PD2-S 116,42.5 r90 bottom value=1uH
L8 "XEL4030-332MEB" XEL4030_310 124.103,62.76 r270 top value=3.3uH
L9 "74279221281" 1206 124.103,66.67 r180 top value="280 ohm"
LBL1 "THT-14-423-10" Label_650x200 134.993,6.2 r0 top
Logo1 "CE Mark" CE_Mark_5mm 119.083,15.223 r0 top
Logo2 "Texas Instruments" TI_Stacked_Overlay_Small 97.063,15.796 r0 top
Logo3 "FCC disclaimer" FCC_disclaimer 103.244,10.844 r0 top
Logo4 "WEEE logo" WEEE_Minimum 111.737,16.308 r0 top
LOGO5 "DANGER HIGH VOLTAGE" IEC_HighVoltage_Medium 116,107.5 r0 top
LOGO6 "DANGER HIGH VOLTAGE" IEC_HighVoltage_Medium 118.5,139 r180 bottom
LOGO7 "DANGER HIGH VOLTAGE" IEC_HighVoltage_Medium 44.75,139 r180 bottom
LOGO8 "DANGER HIGH VOLTAGE" IEC_HighVoltage_Medium 10.743,34.365 r0 top
LOGO9 "DANGER HIGH VOLTAGE" IEC_HighVoltage_Medium 35.5,69 r180 bottom
NT1 "Net-Tie" Net-Tie_0805_HV_NoOverlay 131.275,49.804 r90 top net-tie
Q1 "BSC500N20NS3G" FP-BSC220N20NSFDATMA1_TSON-8-MFG 107.808,44.45 r180 bottom
Q2 "IPD95R2K0P7ATMA1" FP-IPD95R2K0P7ATMA1_DPAK-MFG 62.444,57.02 r180 bottom
Q3 "CSD17585F5T" YJK0003A#1 109.503,68.56 r270 top value=30V
Q4 "IRFIZ24GPBF" FP-IRFIZ24GPBF_TO-220-3-MFG 135.128,70.358 r270 bottom
Q5 "MMBT3904LT1G" SOT-23 115.443,68.25 r180 bottom value="40 V"
Q6 "CSD17585F5T" YJK0003A#2 125.105,51.646 r0 bottom value=30V
Q7 "CSD17585F5T" YJK0003A#1 84.734,90.135 r270 top value=30V
Q8 "CSD17585F5T" YJK0003A#1 138.182,78.779 r90 top value=30V
R1 "ERJ-6GEYJ102V" 0805_HV 102.973,60.45 r0 bottom value=1.0k
R2 "CRCW1206470KJNEA" 1206 31.263,58.56 r90 bottom value=470k
R3 "CRCW080510K0FKEA" 0805_HV 24.753,45.18 r0 bottom value=10.0k
R4 "CRCW1206470KJNEA" 1206 55.918,49.05 r270 bottom value=470k
R5 "CRCW12061M00JNEA" 1206 55.675,24.971 r180 bottom value=1.0Meg
R6 "ERJ-6GEYJ102V" 0805_HV 102.973,52.89 r0 bottom value=1.0k
R7 "CRCW1206470KJNEA" 1206 31.263,47.97 r90 bottom value=470k
R8 "CRCW12061M00JNEA" 1206 61.109,24.971 r180 bottom value=1.0Meg
R9 "CRCW1206470KJNEA" 1206 31.263,26.79 r270 bottom value=470k
R10 "CRCW080510K0FKEA" 0805_HV 24.753,25.2 r0 bottom value=10.0k
R11 "CRCW120610R0JNEA" 1206 55.813,55.17 r180 bottom value=10
R12 "CRCW1206470KJNEA" 1206 31.263,37.38 r270 bottom value=470k
R13 "CRCW12061M00JNEA" 1206 60.873,15.84 r90 bottom value=1.0Meg
R14 "RC1206JR-070RL" 1206 129.062,43.985 r0 bottom value=0
R15 "CRCW080510K0FKEA" 0805_HV 24.628,11.605 r0 bottom value=10.0k
R16 "CRCW1206470KJNEA" 1206 31.263,16.2 r90 bottom value=470k
R17 "CRCW12061M00JNEA" 1206 55.983,15.84 r270 bottom value=1.0Meg
R18 "RC1206JR-070RL" 1206 119.75,42.5 r90 bottom value=0
R19 "CRCW1206470KJNEA" 1206 31.263,5.61 r90 bottom value=470k
R20 "RC0603FR-074K7L" 0603 125.984,27.432 r0 top value=4.70k
R21 "CRCW0805100RFKEA" 0805_HV 104.1,65.1 r180 top value=100
R22 "CRCW060349R9FKEA" 0603 102.457,26.56 r180 bottom value=49.9
R23 "CRCW12061K00JNEA" 1206 101.643,42.87 r90 bottom value=1.0k
R24 "CRCW080520R0JNEA" 0805_HV 83.7,39.4 r0 bottom value=20
R25 "CRCW06032K49FKEA" 0603 98.763,35.82 r270 bottom value=2.49k
R26 "CRCW06036K81FKEA" 0603 100.443,35.82 r270 bottom value=6.81k
R27 "ERJ-6ENF6042V" 0805_HV 65.433,37.41 r0 bottom value=60.4k
R28 "RC0603FR-0738K3L" 0603 102.457,28.22 r0 bottom value=38.3k
R29 "ERJ-6ENF6042V" 0805_HV 59.433,45.54 r180 top value=60.4k
R30 "RC0603FR-0710KL" 0603 98.643,28.22 r0 bottom value=10.0k
R31 "CRCW0603100KFKEA" 0603 107.793,30.81 r0 top value=100k
R32 "RC0603FR-0733K2L" 0603 59.793,47.58 r0 top value=33.2k
R33 "RC0603FR-0710KL" 0603 98.643,29.88 r0 bottom value=10.0k
R34 "CRCW06031K00FKEA" 0603 58.524,50.37 r270 top value=1.00k
R35 "CSRN2010FKR500" 2010 60.123,41.07 r90 bottom value=0.5
R36 "RC0603FR-0733KL" 0603 63.333,45.792 r180 top value=33.0k
R37 "RC0603FR-074K7L" 0603 63.333,44.06 r0 top value=4.70k
R38 "CRCW0603100KFKEA" 0603 104.074,67.042 r180 top value=100k
R39 "CRCW0603100RJNEA" 0603 56.31,90.996 r270 bottom value=100
R40 "RC0603FR-0710KL" 0603 109.503,68.01 r90 bottom value=10.0k
R41 "RC0603FR-074K7L" 0603 118.293,55.21 r90 bottom value=4.70k
R42 "CRCW06034R99FKEA" 0603 118.293,68.18 r90 bottom value=4.99
R43 "RC0603FR-0710KL" 0603 117.453,65.63 r0 bottom value=10.0k
R44 "RC0603FR-0710KL" 0603 113.253,71.88 r0 bottom value=10.0k
R45 "RC0603FR-0711K8L" 0603 117.453,62.37 r0 bottom value=11.8k
R46 "CRCW06031K00FKEA" 0603 117.453,63.98 r180 bottom value=1.00k
R47 "CRCW06031K00FKEA" 0603 114.903,64.86 r270 bottom value=1.00k
R48 "RC0603FR-074K7L" 0603 106.099,71.21 r270 bottom value=4.70k
R49 "CRCW0603100RFKEA" 0603 120.753,58.74 r180 top value=100
R50 "RC0603FR-0710KL" 0603 120.753,55.501 r180 top value=10.0k
R51 "CRCW0603100KFKEA" 0603 128.163,52.094 r0 top value=100k
R52 "RC0603FR-07510KL" 0603 128.163,50.43 r0 top value=510k
R53 "RC0603FR-0747KL" 0603 124.944,49.813 r90 top value=47.0k
R54 "RC0603FR-072K7L" 0603 120.753,53.88 r0 top value=2.70k
R55 "RT0603DRE0746K4L" 0603 128.163,55.38 r180 top value=46.4k
R56 "RC0603FR-0710KL" 0603 128.163,48.78 r180 top value=10.0k
R57 "RC0603FR-07620RL" 0603 74.422,96 r180 top value=620
R58 "RC0603FR-0710KL" 0603 93.94,96.33 r0 top value=10.0k
R59 "RC1206JR-070RL" 1206 34.922,98.93 r180 bottom value=0
R60 "RC1206JR-070RL" 1206 34.922,90.18 r180 bottom value=0
R61 "RC1206JR-070RL" 1206 34.922,78.55 r180 bottom value=0
R62 "RC1206JR-070RL" 1206 56.672,100.48 r90 bottom value=0
R63 "RC0402FR-07470RL" 0402 87.076,87.6 r180 top value=470
R64 "RCS06030000Z0EA" 0603 74.422,90.75 r0 top value=0
R66 "RC0603FR-0710KL" 0603 92.434,92.785 r270 top value=10.0k
R67 "RCS06030000Z0EA" 0603 83.756,92.43 r180 top value=0
R68 "RC0603FR-0710KL" 0603 150.172,85.25 r0 bottom value=10.0k
R69 "RC0603FR-0710KL" 0603 141.713,81.989 r270 top value=10.0k
R70 "RCS06030000Z0EA" 0603 150.922,79.75 r270 bottom value=0
R71 "RCS06030000Z0EA" 0603 138.213,85.579 r90 top value=0
R72 "RC0603FR-0710KL" 0603 139.172,85.25 r0 bottom value=10.0k
R73 "RC0603FR-071ML" 0603 136.463,82.029 r270 top value=1.00Meg
R74 "RCS06030000Z0EA" 0603 146.5,79.45 r270 bottom value=0
R75 "RC0603FR-071ML" 0603 139.963,85.579 r270 top value=1.00Meg
R76 "RC0603FR-071ML" 0603 136.463,85.579 r90 top value=1.00Meg
R77 "RC0603FR-0710KL" 0603 127.672,85.25 r0 bottom value=10.0k
R78 "RC0603FR-07150RL" 0603 126.86,85.729 r90 top value=150
R79 "RC0603FR-0711K5L" 0603 128.507,85.729 r270 top value=11.5k
R80 "RC0603FR-0710KL" 0603 116.422,85.25 r0 bottom value=10.0k
R81 "CRCW06031K00FKEA" 0603 131.019,84.888 r180 top value=1.00k
R82 "RC0603JR-0739KL" 0603 58.088,90.996 r270 bottom value=39k
R83 "CRCW1206390KJNEA" 1206 42.414,87.001 r0 bottom value=390k
R84 "CRCW1206390KJNEA" 1206 42.414,90.234 r180 bottom value=390k
R85 "RC0402FR-07470RL" 0402 141.713,78.779 r90 top value=470
R86 "RCS06030000Z0EA" 0603 136.463,78.779 r270 top value=0
R87 "RC1206JR-070RL" 1206 148.75,105.5 r0 bottom value=0
R88 "RC1206JR-070RL" 1206 137.422,105.5 r0 bottom value=0
R89 "RC1206JR-070RL" 1206 126,105.5 r0 bottom value=0
R90 "RC1206JR-070RL" 1206 114.672,105.5 r0 bottom value=0
R92 "RC0603FR-0710KL" 0603 92.434,89.485 r270 top value=10.0k
RT1 "B57153S0479M051" S153 24.663,57.98 r0 top value=4.7
RT2 "B57153S0479M051" S153 24.663,38.1 r0 top value=4.7
RT3 "B57153S0479M051" S153 24.663,18.21 r0 top value=4.7
T1 "750320029" FP-750320029_PTH14_32MM25_27MM05-MFG 84.073,51.84 r0 top
TP1 "5012" Keystone5012 15.813,63.54 r0 top
TP2 "5012" Keystone5012 15.813,43.93 r0 top
TP3 "5012" Keystone5012 15.813,24.32 r0 top
TP4 "5010" Keystone5010 125.984,24.384 r0 top
TP5 "5012" Keystone5012 15.813,4.71 r0 top
TP6 "5000" Keystone5000 102.003,24.12 r90 top
TP7 "5003" Keystone5003 105.603,24.12 r90 top
TP8 "5011" Keystone5011 116.332,24.384 r0 top
TP9 "5001" Keystone5001 78.616,86.5 r90 top
TP10 "5003" Keystone5003 139,24.384 r90 top
TP11 "TP_SM_1MM" TP_SM_1MM 126.723,58.65 r90 top
TP12 "5003" Keystone5003 88.06,96.33 r90 top
TP13 "5003" Keystone5003 66.422,96 r90 top
TP14 "5003" Keystone5003 78.616,92.42 r90 top
TP15 "5003" Keystone5003 100.348,78.75 r90 top
TP16 "5003" Keystone5003 133.5,78.75 r90 top
TP18 "5003" Keystone5003 144,78.75 r90 top
TP21 "5003" Keystone5003 128.75,78.75 r90 top
TP22 "5011" Keystone5011 108.543,78.75 r90 top
U1 "UCC24612-1DBVR" DBV0005A_N 106.853,37.985 r270 bottom
U2 "FOD817A3SD" N04C 89.25,36 r180 bottom
U3 "UCC28742DBVR" DBV0006A_N 63.303,50.28 r180 top
U4 "TL431AIDBZT" DBZ0003A_N 98.643,23.944 r270 bottom
U5 "TL7705AIDR" D0008A_N 123.058,56.745 r180 bottom
U6 "ATL431AQDBZR" DBZ0003A-MFG 108.543,71.61 r90 bottom
U7 "TPS55330RTER" RTE0016C_NV 124.353,55.2 r0 top
U8 "DRV8220DRLR" DRL0006A-MFG 72.406,93 r180 top
U9 "SN74AUP1G08DBVT" DBV0005A_N 88.786,91.47 r180 top
U10 "TSM24CADBZR" DBZ0003A-MFG 150.172,88 r270 bottom
U11 "TLV7021DCKR" DCK0005A_N 134.213,85.579 r270 top
U12 "TSM24CADBZR" DBZ0003A-MFG 139.172,88 r270 bottom
U13 "TSM24CADBZR" DBZ0003A-MFG 127.672,88 r270 bottom
U14 "TL431AQDBVR" DBV0005A_N 127.713,82.079 r180 top
U15 "TSM24CADBZR" DBZ0003A-MFG 116.422,88 r270 bottom
U16 "RES60ADWV" DWV0008A-MFG 145.787,96.45 r270 bottom
U17 "RES60ADWV" DWV0008A-MFG 134.288,96.33 r270 bottom
U18 "RES60ADWV" DWV0008A-MFG 123.079,96.332 r270 bottom
U19 "RES60ADWV" DWV0008A-MFG 111.615,96.3 r270 bottom
U20 "FOD817AS" N04C 51.585,95.16 r0 bottom
ZZ1 "This Assembly Note is for PCB labels only" AssemblyNoteLabel 173.843,5.875 r90 top
ZZ2 "These assemblies are ESD sensitive, ESD precautions shall be observed." AssemblyNote 170.403,45.346 r90 top
ZZ3 "These assemblies must be clean and free from flux and all contaminants. Use of no clean flux is not acceptable." AssemblyNote 166.593,5.926 r90 top
ZZ4 "These assemblies must comply with workmanship standards IPC-A-610 Class 2, unless otherwise specified." AssemblyNote 162.813,14.206 r90 top

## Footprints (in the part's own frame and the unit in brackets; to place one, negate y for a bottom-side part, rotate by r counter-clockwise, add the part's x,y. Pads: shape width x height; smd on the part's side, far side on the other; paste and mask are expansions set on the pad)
0402 [mm] "0402 from SM-752 data"
  rect 0.8x0.6 smd: 1(-0.6,0) 2(0.6,0)
  silkscreen extent -1.22,-0.52 1.22,0.52, body extent -0.55,-0.3 0.55,0.3, height 0.6
0603 [mm] "0603 from SM-752 data"
  rect 1x0.95 smd: 1(-0.8,0) 2(0.8,0)
  silkscreen extent -1.52,-0.69 1.52,0.69, body extent -0.87,-0.47 0.87,0.47, height 1
0603S [mil]
  rect 20x35 smd: 1(-30,0) 2(30,0)
  body extent -34,-19 34,19, height 39
0805_HV [mil] "0805 with 30mil clearance between pads"
  rect 50x63 smd: 1(-40,0) 2(40,0)
  silkscreen extent -74,-40 74,40, body extent -43,-29 43,29, height 57
1206 [mm] "1206 from SM-752 data"
  rect 1.3x1.85 smd: 1(-1.45,0) 2(1.45,0)
  silkscreen extent -2.4,-1.21 2.4,1.21, body extent -1.7,-0.9 1.7,0.9, height 1.35
1206_180 [mm] "1206_180"
  rect 1.1x1.6 smd: 1(-1.7,0) 2(1.7,0)
  silkscreen extent -0.9,-1 0.9,1, body extent -1.75,-0.95 1.75,0.95, height 1.8
1210_270 [mm] "1210"
  rect 1.3x2.7 smd: 1(-1.45,0) 2(1.45,0)
  silkscreen extent -2.32,-1.57 2.32,1.57, body extent -1.7,-1.35 1.7,1.35, height 2.7
1812_254 [mm] "SMD, 2-Leads, Body 4.8x3.4mm"
  rect 1.6x3.4 smd: 1(-2,0) 2(2,0)
  silkscreen extent -0.8,-1.7 0.8,1.7, body extent -2.4,-1.7 2.4,1.7, height 2.54
2010 [mm] "Chip Capacitor, Body 5.08x2.54mm, IPC Medium Density"
  rect 1.6x2.7 smd: 1(-2.3,0) 2(2.3,0)
  silkscreen extent -3.42,-1.65 3.42,1.65, body extent -2.73,-1.45 2.73,1.45, height 1.66
AssemblyNote [mm] "Assembly Note"
AssemblyNoteLabel [mm] "Assembly Note for PCB Labels"
B32923_20.5mm [mm] "Epcos film capacitors, 22.5mm spacing"
  rect 1.5x1.5 hole 1: 1(-11.25,0)
  round 1.5 hole 1: 2(11.25,0)
  silkscreen extent -13.25,-5.5 13.25,5.5, body extent -13.25,-5.5 13.25,5.5, height 20.5
CE_Mark_5mm [mm] "Minimum text height for CE Mark"
  silkscreen extent -3.5,-2.5 3.5,2.5
D0008A_N [mm] "SOIC, 8-Leads, Body 4.9x3.9mm, Pitch 1.27mm, IPC Medium Density"
  oval 1.45x0.6 smd: 1(-2.725,1.905) 2(-2.725,0.635) 3(-2.725,-0.635) 4(-2.725,-1.905) 5(2.725,-1.905) 6(2.725,-0.635) 7(2.725,0.635) 8(2.725,1.905)
  silkscreen extent -3.3,-2.5 0.9,2.5, body extent -3,-2.45 3,2.45, height 1.63
DBV0005A_N [mm] "SOT23, 5-Leads, Body 2.9x1.6mm, Pitch 0.95mm, Lead Span 2.8mm, IPC Medium Density"
  rrect17% 1x0.6 smd: 1(-1.375,0.95) 2(-1.375,0) 3(-1.375,-0.95) 4(1.375,-0.95) 5(1.375,0.95)
  silkscreen extent -0.25,-1.55 0.25,1.55, body extent -1.42,-1.46 1.42,1.46, height 1.09
DBV0006A_N [mm] "SOT23, 6-Leads, Body 2.9x1.6mm, Pitch 0.95mm, Lead Span 2.8mm, IPC Medium Density"
  rrect17% 1x0.6 smd: 1(-1.375,0.95) 2(-1.375,0) 3(-1.375,-0.95) 4(1.375,-0.95) 5(1.375,0) 6(1.375,0.95)
  silkscreen extent -1.68,-1.55 0.5,1.55, body extent -1.42,-1.46 1.42,1.46, height 1.12
DBZ0003A-MFG [mm] "Recommended Land Pattern"
  rrect17% 1.3x0.6 smd paste+0 mask+0: 1(-1.05,0.95) 2(-1.05,-0.95) 3(1.05,0)
  silkscreen extent -0.03,-1.52 0.7,1.52, body extent -1.18,-1.46 1.18,1.46, height 1.12
DBZ0003A_N [mm] "SOT23, 3-Leads, Body 2.9x1.3mm, Pitch 0.95mm, Lead Span 2.4mm, IPC Medium Density"
  rrect17% 1x0.6 smd: 1(-1.2,0.95) 2(-1.2,-0.95) 3(1.2,0)
  silkscreen extent 0.2,-1.5 0.7,1.5, body extent -1.26,-1.46 1.26,1.46, height 0.98
DCK0005A_N [mm] "SOT353, 5-Leads, Body 2x1.3mm, Pitch 0.65mm, Lead Span 2.1mm, IPC Medium Density"
  rrect25% 0.85x0.4 smd: 1(-1.125,0.65) 2(-1.125,0) 3(-1.125,-0.65) 4(1.125,-0.65) 5(1.125,0.65)
  silkscreen extent -1.48,-1.02 0.55,1.1, body extent -1.14,-1 1.14,1, height 0.95
DRL0006A-MFG [mm]
  rrect33% 0.67x0.3 smd paste+0 mask+0: 1(-0.74,0.5) 2(-0.74,0) 3(-0.74,-0.5) 4(0.74,-0.5) 5(0.74,0) 6(0.74,0.5)
  silkscreen extent -1.9,-1.05 0.65,1.05, body extent -1.17,-1.1 1.17,1.1, height 0.25
DWV0008A-MFG [mm]
  rrect17% 1.8x0.6 smd paste+0 mask+0: 1(-5.45,1.905) 2(-5.45,0.635) 3(-5.45,-0.635) 4(-5.45,-1.905) 5(5.45,-1.905) 6(5.45,-0.635) 7(5.45,0.635) 8(5.45,1.905)
  silkscreen extent -7.02,-2.98 3.8,2.98, body extent -5.75,-2.93 5.75,2.93, height 2.8
FCC_disclaimer [mm]
Fiducial10-20 [mm]
  round 1 smd mask+0.5: 1(0,0)
  Top Layer keep-out circle w1.178: c0,0 r0.5
FP-750320029_PTH14_32MM25_27MM05-MFG [mm]
  rrect5% 2.02x2.02 hole 1.32 paste-2539.97 mask+0: 1(-12.7,11.43)
  round 2.02 hole 1.32 paste-2539.97 mask+0: 2(-12.7,7.62) 3(-12.7,3.81) 4(-12.7,0) 5(-12.7,-3.81) 6(-12.7,-7.62) 7(-12.7,-11.43) 8(12.7,-11.43) 9(12.7,-7.62) 10(12.7,-3.81) 11(12.7,0) 12(12.7,3.81) 13(12.7,7.62) 14(12.7,11.43)
  silkscreen extent -16.85,-13.52 16.12,13.52, body extent -16.22,-13.62 16.22,13.62, height 0.25
FP-7446121007_PTH_CMC_18MM5_13MM5-MFG [mm] "Recommended Land Pattern"
  rrect6% 1.7x1.7 hole 1.1 paste-2539.97 mask+0: 1(-7.5,-5)
  round 1.7 hole 1.1 paste-2539.97 mask+0: 2(7.5,-5) 3(7.5,5) 4(-7.5,5)
  silkscreen extent -9.25,-7.37 9.25,6.75, body extent -9.35,-6.85 9.35,6.85, height 0.25
FP-61301821121_HDR18-MFG [mm] "Recommended Land Pattern"
  rrect6% 1.7x1.7 hole 1.1 paste-2539.97 mask+0: 1(-10.16,-1.27)
  round 1.7 hole 1.1 paste-2539.97 mask+0: 2(-10.16,1.27) 3(-7.62,-1.27) 4(-7.62,1.27) 5(-5.08,-1.27) 6(-5.08,1.27) 7(-2.54,-1.27) 8(-2.54,1.27) 9(0,-1.27) 10(0,1.27) 11(2.54,-1.27) 12(2.54,1.27) 13(5.08,-1.27) 14(5.08,1.27) 15(7.62,-1.27) 16(7.62,1.27) 17(10.16,-1.27) 18(10.16,1.27)
  silkscreen extent -11.58,-3.22 11.58,2.62, body extent -11.68,-2.72 11.68,2.72, height 0.25
FP-BSC220N20NSFDATMA1_TSON-8-MFG [mm]
  rrect10% 3.08x1 smd paste-1000 mask-1000: 1-2-3(-0.635,-2.75)
  rrect19% 0.54x1 smd paste-1000 mask+0: 4(1.905,-2.75)
  rrect2% 4.45x4.4 smd paste-1000 mask-1000: 5-6-7-8(0,1.05)
  silkscreen extent -2.5,-4.02 2.5,-1.53, body extent -2.5,-3.01 2.5,3.01, height 1.1
FP-BZX384C43-E3-08_SOD323-MFG [mm] "Recommended Land Pattern"
  rrect17% 0.8x0.6 smd paste+0 mask+0: 1(-1.2,0) 2(1.2,0)
  silkscreen extent -2.27,-0.75 0.97,0.75, body extent -1.35,-0.65 1.35,0.65, height 1.15
FP-CC0603KRX7R7BB224_0603-MFG [mm]
  rrect13% 0.8x0.9 smd paste+0 mask+0: 1(-0.75,0) 2(0.75,0)
  silkscreen extent -0.85,-0.85 0.85,0.85, body extent -0.8,-0.4 0.8,0.4, height 0.9
FP-DE1E3RA332MN4AP01F_RADIAL_CAP_10MM0_5MM0_10MM0-MFG [mm] "Recommended Land Pattern"
  rrect8% 1.3x1.3 hole 0.8 paste-2539.97 mask+0: 1(-5,0)
  round 1.3 hole 0.8 paste-2539.97 mask+0: 2(5,0)
  silkscreen extent -5,-2.5 5,2.5, body extent -5.5,-2.5 5.5,2.5, height 13
FP-FCR7350G_CONN_BANANA_JACK-MFG#1 [mm]
  rrect3% 3.35x3.35 hole 2.2 unplated paste-2539.97 mask+0: 1(11,0)
  round 1.85 hole 1.2 paste-2539.97 mask+0: 2(4.64,5.08) 3(14.8,5.08) 4(4.64,-5.08) 5(14.8,-5.08)
  silkscreen extent -1.83,-6.05 17.2,6.05, body extent -16.7,-6.15 16.7,6.15, height 0.25
FP-FCR7350G_CONN_BANANA_JACK-MFG#2 [mm]
  rrect3% 3.35x3.35 hole 2.2 paste-2539.97 mask+0: 1(11,0)
  round 1.85 hole 1.2 paste-2539.97 mask+0: 2(4.64,5.08) 3(14.8,5.08) 4(4.64,-5.08) 5(14.8,-5.08)
  silkscreen extent -1.83,-6.05 17.2,6.05, body extent -16.7,-6.15 16.7,6.15, height 0.25
FP-FCR7350N_CONN_BANANA_JACK-MFG#1 [mm]
  rrect3% 3.35x3.35 hole 2.2 unplated paste-2539.97 mask+0: 1(11,0)
  round 1.85 hole 1.2 paste-2539.97 mask+0: 2(4.64,5.08) 3(14.8,5.08) 4(4.64,-5.08) 5(14.8,-5.08)
  silkscreen extent -1.83,-6.05 17.2,6.05, body extent -16.7,-6.15 16.7,6.15, height 0.25
FP-FCR7350N_CONN_BANANA_JACK-MFG#2 [mm]
  rrect3% 3.35x3.35 hole 2.2 paste-2539.97 mask+0: 1(11,0)
  round 1.85 hole 1.2 paste-2539.97 mask+0: 2(4.64,5.08) 3(14.8,5.08) 4(4.64,-5.08) 5(14.8,-5.08)
  silkscreen extent -1.83,-6.05 17.2,6.05, body extent -16.7,-6.15 16.7,6.15, height 0.25
"FP-G9KC-4A1B DC12_PTH_RELAY_58MM0_35MM0-MFG" [mm] "Recommended Land Pattern"
  rrect6% 1.6x3.1 hole 2.5 slot 1 at 0 deg paste-2539.97 mask+0: 1(-26.9,-14.4)
  rrect100% 2.2x11.6 hole 11 slot 1.6 at 0 deg paste-2539.97 mask+0: 2(-14,-10.5) 3(-0.5,-10.5) 4(13,-10.5) 5(26.5,-10.5) 6(26.5,10.5) 7(13,10.5) 8(-0.5,10.5) 9(-14,10.5)
  rrect100% 1.6x3.1 hole 2.5 slot 1 at 0 deg paste-2539.97 mask+0: 10(-26.9,14.4) 11(-26.9,7.3) 12(-26.9,-7.3)
  silkscreen extent -29.25,-18.38 29.25,17.75, body extent -29,-17.5 29,17.5, height 47.51
FP-GSRB751S-40_SOD523-0 [mm]
  rrect17% 0.6x0.7 smd paste+0 mask+0: 1(-0.71,0) 2(0.71,0)
  silkscreen extent -1.16,-0.43 0.04,0.95, body extent -0.8,-0.4 0.8,0.4, height 0.77
FP-IPD95R2K0P7ATMA1_DPAK-MFG [mm]
  rrect8% 1.2x2.2 smd paste-1000 mask+0: 1(-2.28,-5.12) 3(2.28,-5.12)
  rrect2% 5.8x6.4 smd paste-1000 mask+0: 4(0,1.18)
  silkscreen extent -3.35,-3.1 3.35,3.1, body extent -3.27,-5.79 3.27,4.15, height 2.42
FP-IRFIZ24GPBF_TO-220-3-MFG [mm] "Recommended Land Pattern"
  rrect5% 1.9x1.9 hole 1.25 paste-2539.97 mask+0: 1(-0.597,2.54)
  round 1.9 hole 1.25 paste-2539.97 mask+0: 2(-0.597,0) 3(-0.597,-2.54)
  silkscreen extent -2.41,-5.35 2.41,5.77, body extent -2.35,-5.25 2.35,5.25, height 19.62
FP-PHE850ED6100MD18R06L2_RADIAL-MFG [mm]
  rrect7% 1.45x1.45 hole 0.95 paste-2539.97 mask+0: 1(-11.25,0)
  round 1.45 hole 0.95 paste-2539.97 mask+0: 2(11.25,0)
  silkscreen extent -13,-5.25 13,5.25, body extent -13.1,-5.35 13.1,5.35, height 0.25
FP-PHVL-3R9V255-R_RADIAL-MFG [mm]
  rrect8% 1.3x1.3 hole 0.8 paste-2539.97 mask+0: 1(-2.65,0)
  round 1.3 hole 0.8 paste-2539.97 mask+0: 2(2.65,0)
  silkscreen extent -10.9,-5.75 10.9,5.75, body extent -11,-5.85 11,5.85, height 0.25
FP-SMCJ130A_DO-214AB-MFG [mm] "Recommended Land Pattern"
  rrect4% 2.4x3.3 smd paste+0 mask+0: 1(-3.3,0) 2(3.3,0)
  silkscreen extent -5.27,-3.11 3.55,3.11, body extent -3.97,-2.95 3.97,2.95, height 2.62
FP-VY2102M29Y5US6TV7_RADIAL-MFG [mm]
  rrect8% 1.3x1.3 hole 0.8 paste-2539.97 mask+0: 1(-3.75,0)
  round 1.3 hole 0.8 paste-2539.97 mask+0: 2(3.75,0)
  silkscreen extent -3.75,-2.5 3.75,2.5, body extent -4.52,-2.51 4.52,2.5, height 11.5
FUSE_0443 [mm] "LITTELFUSE"
  rect 3.25x3.43 smd: 1(-4.675,0) 2(4.675,0)
  silkscreen extent -2.7,-1.7 2.7,1.7, body extent -5.05,-1.56 5.05,1.56, height 3.12
IEC_HighVoltage_Medium [mm]
  silkscreen extent -5.51,-4.46 5.51,5.09
Keystone5000 [mil] "For Keystone 500x miniature loop terminals"
  round 80 hole 40: 1(0,0)
  silkscreen extent -52,-52 52,52, body extent -49,-49 49,49, height 182
Keystone5001 [mil] "For Keystone 500x miniature loop terminals"
  round 80 hole 40: 1(0,0)
  silkscreen extent -52,-52 52,52, body extent -49,-49 49,49, height 182
Keystone5003 [mil] "For Keystone 500x miniature loop terminals"
  round 80 hole 40: 1(0,0)
  silkscreen extent -52,-52 52,52, body extent -49,-49 49,49, height 182
Keystone5010 [mil] "Keystone Multipurpose loops"
  round 87 hole 63: 1(0,0)
  silkscreen extent -70,-70 70,70, body extent -63,-63 63,62, height 319
Keystone5011 [mil] "Keystone Multipurpose loops"
  round 87 hole 63: 1(0,0)
  silkscreen extent -70,-70 70,70, body extent -63,-63 63,62, height 319
Keystone5012 [mil] "Keystone Multipurpose loops"
  round 87 hole 63: 1(0,0)
  silkscreen extent -70,-70 70,70, body extent -63,-63 63,62, height 319
Label_650x200 [mil] "Thermal Transfer Label"
  round 1 on Mech13: 0(0,0)
  silkscreen extent -325,-100 325,100, body extent -325,-100 325,100, height 1
N04C [mm] "FAIRCHILD"
  rect 1.3x1.5 smd mask+0.065: 1(-4.587,1.27) 2(-4.612,-1.27) 3(4.588,-1.27) 4(4.613,1.27)
  silkscreen extent -3.56,-2.3 3.56,2.72, body extent -5.08,-2.3 5.08,2.29, height 3.87
Net-Tie_0805_HV_NoOverlay [mil] "0805_HV pads tied by 10mil copper trace which can be cut.  An 0805 part can be placed on pads."
  rect 50x63 smd paste-25: 1(-40,0) 2(40,0)
  Top Layer lines w10: -16,0 16,0
  Top Layer keep-out lines w1: -22,30.91 -22,-30.91 ; -14.96,30.91 14.96,30.91 ; 22,30.91 22,-30.91 ; -14.96,-30.91 14.96,-30.91
"NY PMS 440 0025 PH" [mm] "4-40 nylon screw and mounting hole"
  round 8 hole 3.2: 1(0,0)
  body extent -3.3,-3.3 3.3,3.3, height 2.69
RTE0016C_NV [mm] "Texas Insturments"
  rrect42% 0.6x0.24 smd: 1(-1.4,0.75) 2(-1.4,0.25) 3(-1.4,-0.25) 4(-1.4,-0.75) 9(1.4,-0.75) 10(1.4,-0.25) 11(1.4,0.25) 12(1.4,0.75)
  rrect42% 0.24x0.6 smd: 5(-0.75,-1.4) 6(-0.25,-1.4) 7(0.25,-1.4) 8(0.75,-1.4) 13(0.75,1.4) 14(0.25,1.4) 15(-0.25,1.4) 16(-0.75,1.4)
  rrect6% 1.55x1.55 on Top Paste: 17(0,0)
  rrect6% 1.68x1.68 smd paste-0.85: 17(0,0)
  silkscreen extent -1.72,-1.73 1.72,1.73, body extent -1.57,-1.57 1.58,1.58, height 0.81
S153 [mm] "EPCOS"
  round 1.45 hole 0.8: 1(-2.5,0) 2(2.5,0)
  silkscreen extent -4.2,-3 4.2,3, body extent -4.23,-3 4.23,3, height 12.99
SMA [mm] "Molded Diode, 2-Leads, Body 4.3x2.6mm, IPC Medium Density, based on OnSemi component dimensions and land pattern"
  rect 2x2 smd: 1(-2,0) 2(2,0)
  silkscreen extent -3.66,-1.57 2.79,1.57, body extent -2.6,-1.3 2.6,1.3, height 2.42
SMB [mm] "Molded Diode, 2-Leads, Body 5.4x3.6mm, IPC Medium Density, based on OnSemi component dimensions"
  rect 2.159x2.743 smd: 1(-2.21,0) 2(2.21,0)
  silkscreen extent -3.94,-2.08 3.18,2.08, body extent -2.7,-1.8 2.7,1.8, height 2.32
SOD-123 [mm] "On Semi recommended land pattern"
  rect 0.915x1.22 smd: 1(-1.637,0) 2(1.637,0)
  silkscreen extent -2.74,-1.17 2.03,1.17, body extent -1.93,-0.9 1.93,0.9, height 1.35
SOD-323 [mm] "NXP recommended land pattern"
  rect 0.6x0.6 smd paste-0.05: 1(-1.1,0) 2(1.1,0)
  silkscreen extent -2.06,-0.86 1.53,0.86, body extent -1.3,-0.67 1.3,0.68, height 1.1
SOT-23 [mm] "SOT23, 3-Leads, Body 2.9x1.3mm, Pitch 0.95mm, Lead Span 2.5mm, IPC Medium Density"
  rrect50% 1x0.6 smd: 1(-1.2,0.95) 2(-1.2,-0.95) 3(1.2,0)
  silkscreen extent -1.63,-1.5 0.7,1.5, body extent -1.16,-1.45 1.21,1.45, height 1
TBS4 [mm] "Micro Commercial Components"
  rrect6% 1.8x2 smd: 1(-3.675,2.55) 2(-3.675,-2.55) 3(3.675,-2.55) 4(3.675,2.55)
  silkscreen extent -3.8,-3.45 3.8,3.45, body extent -4.3,-3.35 4.3,3.35, height 1.51
TI_Stacked_Overlay_Small [mm]
  silkscreen extent -10.63,-2.49 10.63,2.49
TP_SM_1MM [mm] "1mm Test Point, SMT"
  round 1 smd paste-0.5: 1(0,0)
WCAP-ATG5_D16H25 [mm] "Aluminum Electrolytic Capacitors, 16x25mm"
  rrect50% 1.65x1.65 hole 1.1: 1(3.75,0)
  round 1.65 hole 1.1: 2(-3.75,0)
  silkscreen extent -8.25,-8.25 8.25,8.25, body extent -7.99,-8 8,8, height 25.31
WCAP-ATG8_D6.3H11 [mm] "Aluminum Electrolytic Capacitors, 6.3x11mm"
  rrect50% 1.3x1.3 hole 0.8: 1(1.25,0)
  round 1.3 hole 0.8: 2(-1.25,0)
  silkscreen extent -3.4,-3.4 3.4,3.4, body extent -3.14,-3.15 3.15,3.15, height 11.31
